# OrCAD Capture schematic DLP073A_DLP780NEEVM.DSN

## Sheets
1 PG05 INPUT FMC CONNECTOR: size D
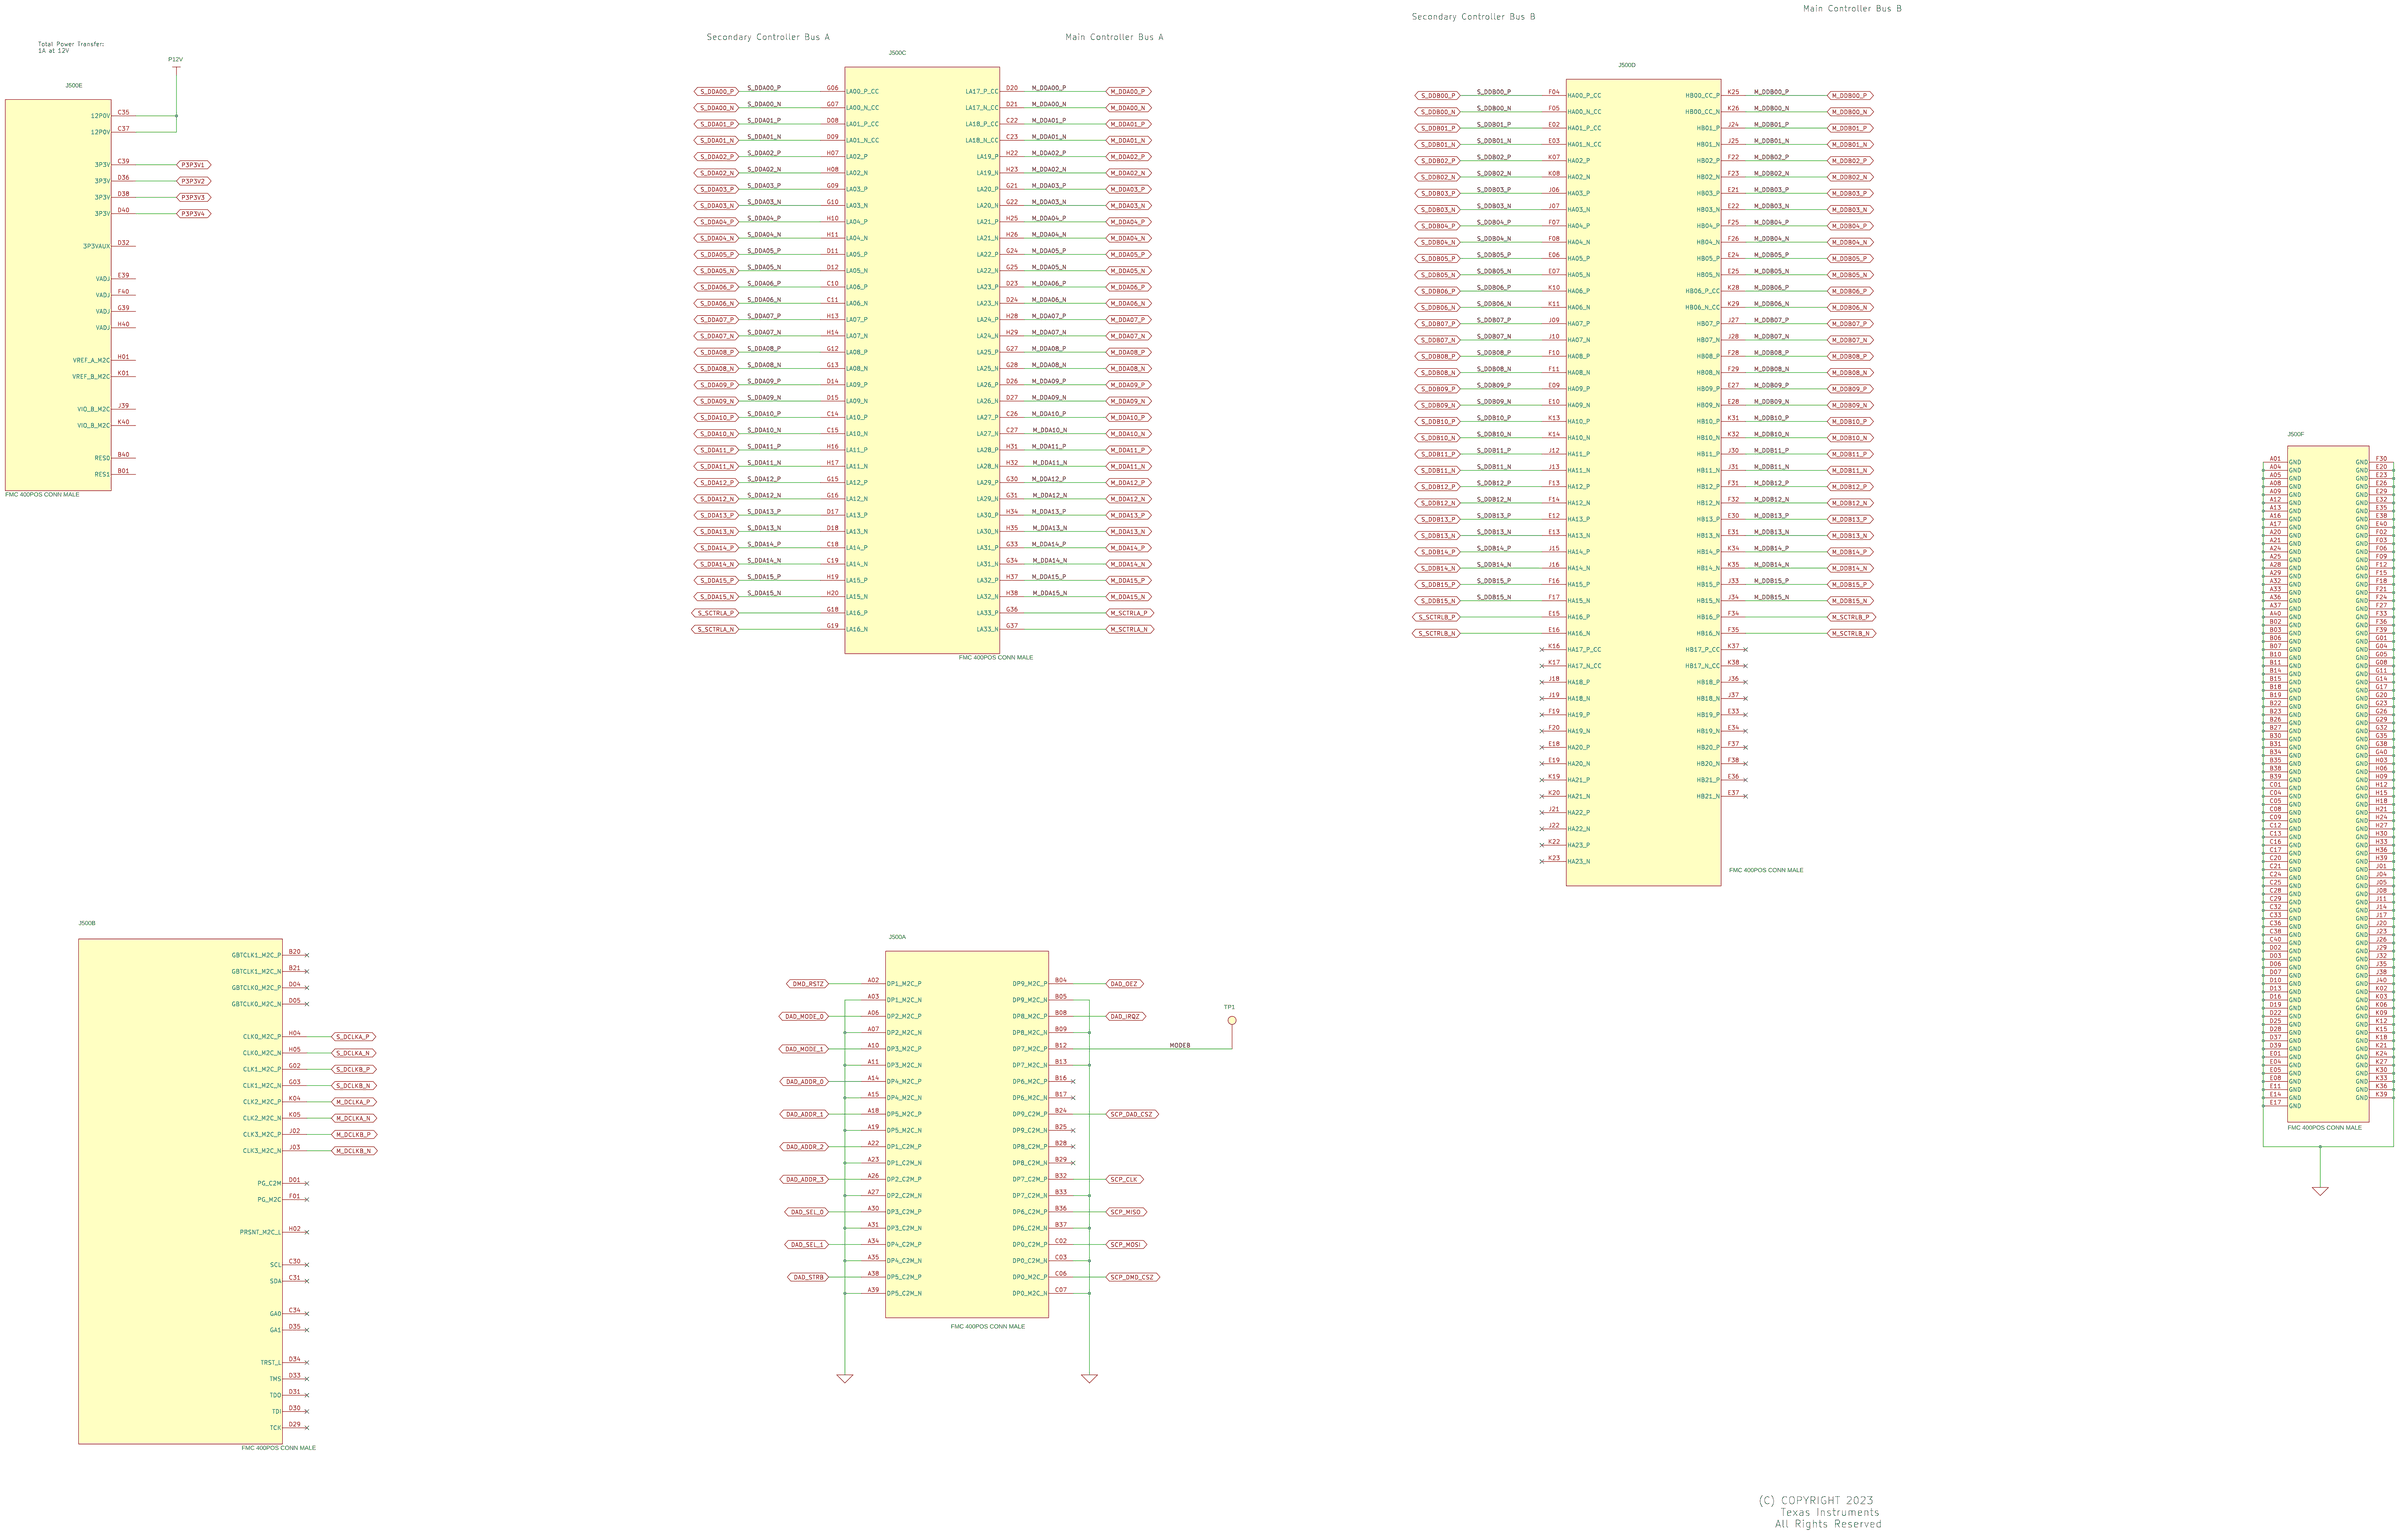
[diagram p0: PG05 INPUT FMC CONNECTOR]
2 PG01 TITLE: rev: D
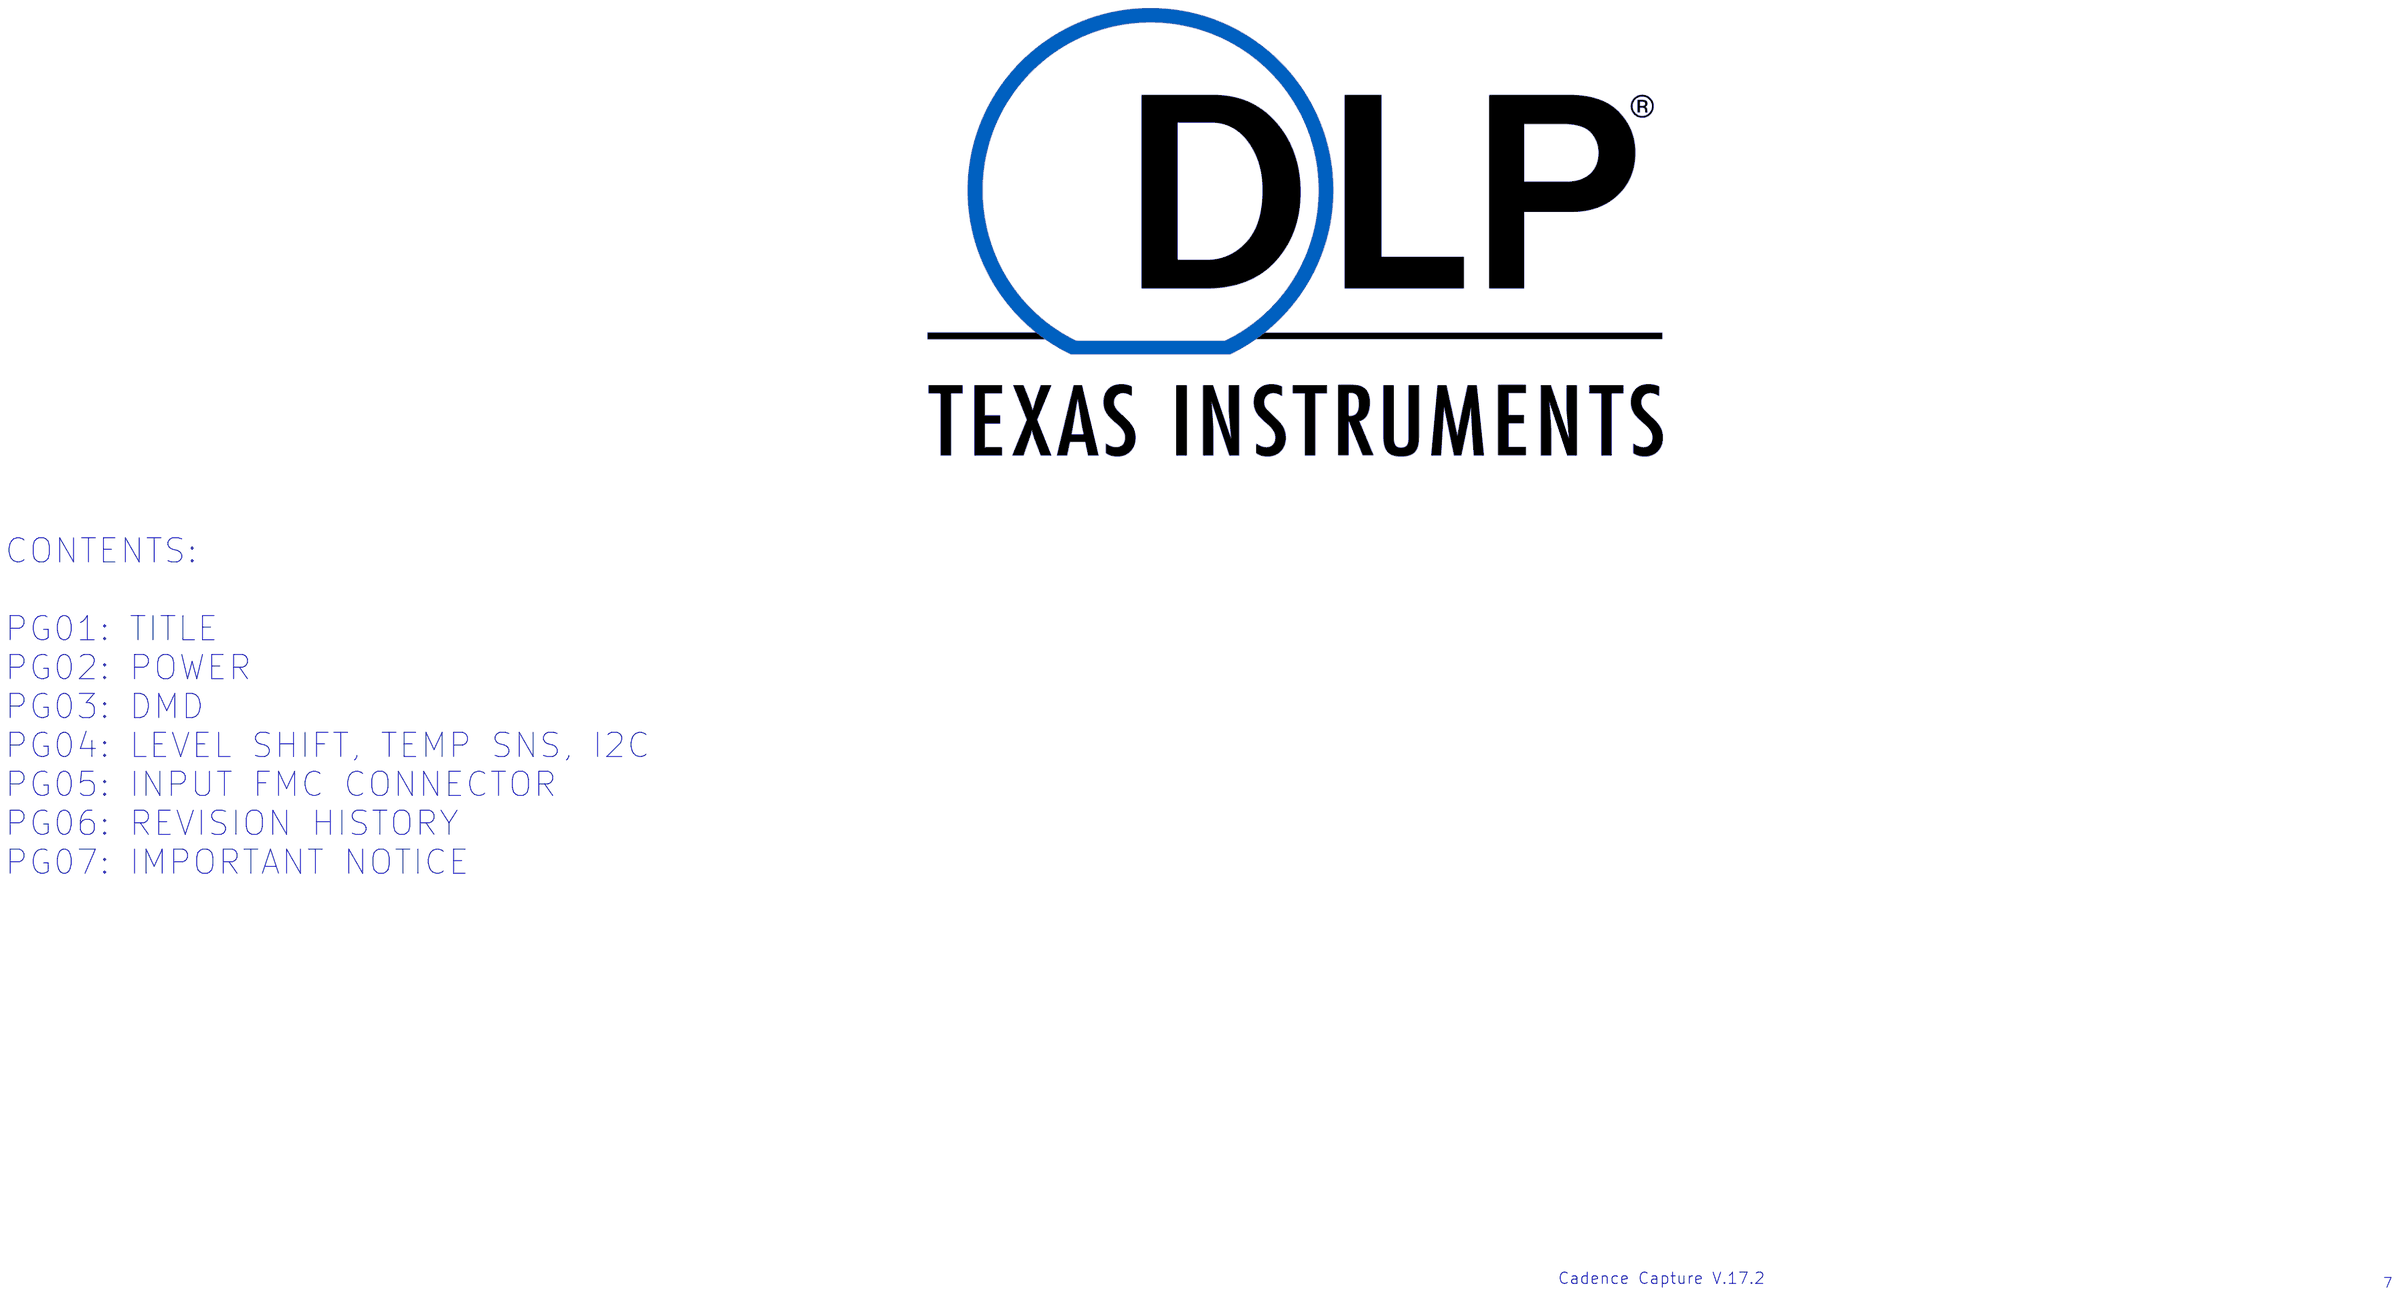
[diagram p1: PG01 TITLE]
3 PG06 REVISION HISTORY: rev: E.2
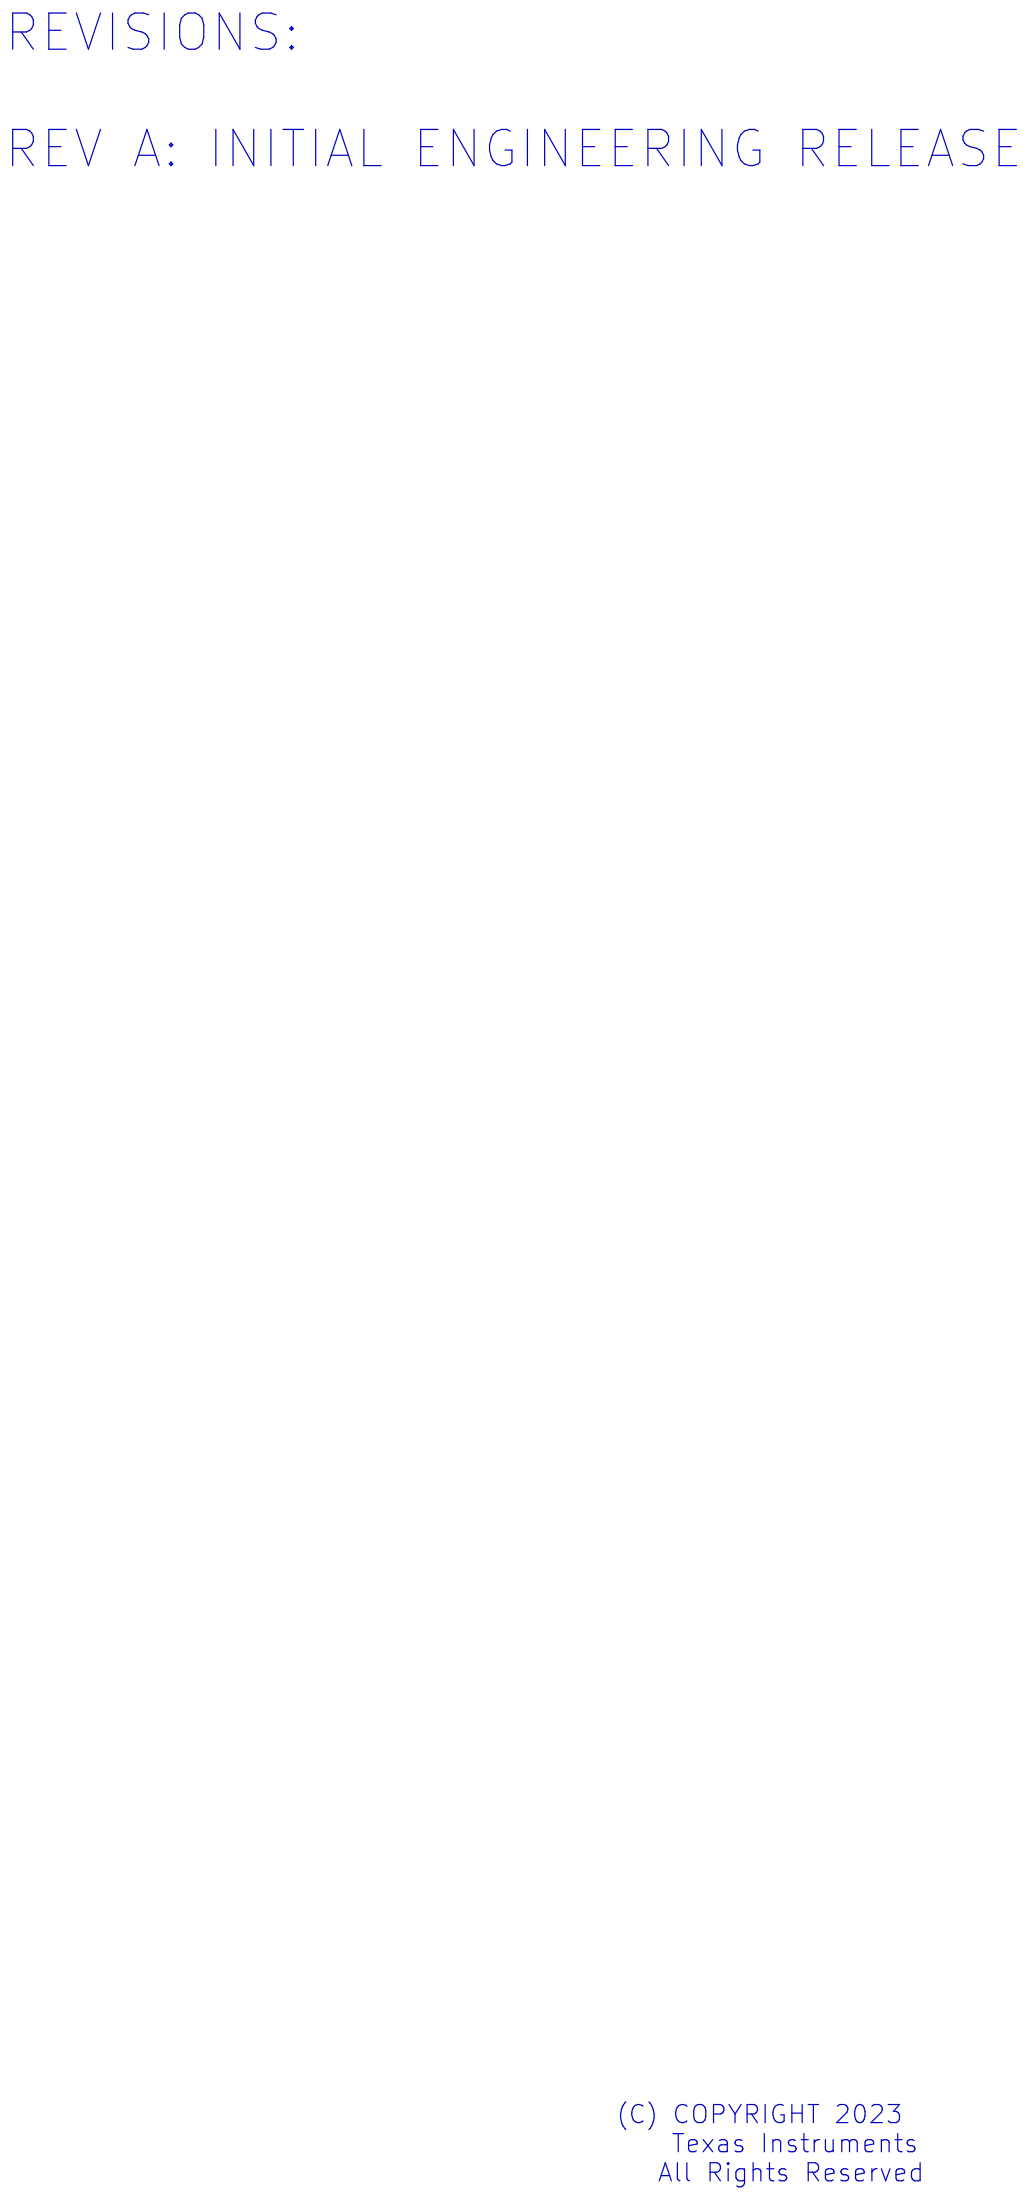
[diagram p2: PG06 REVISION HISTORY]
4 PG02 POWER: size C; rev: E.2
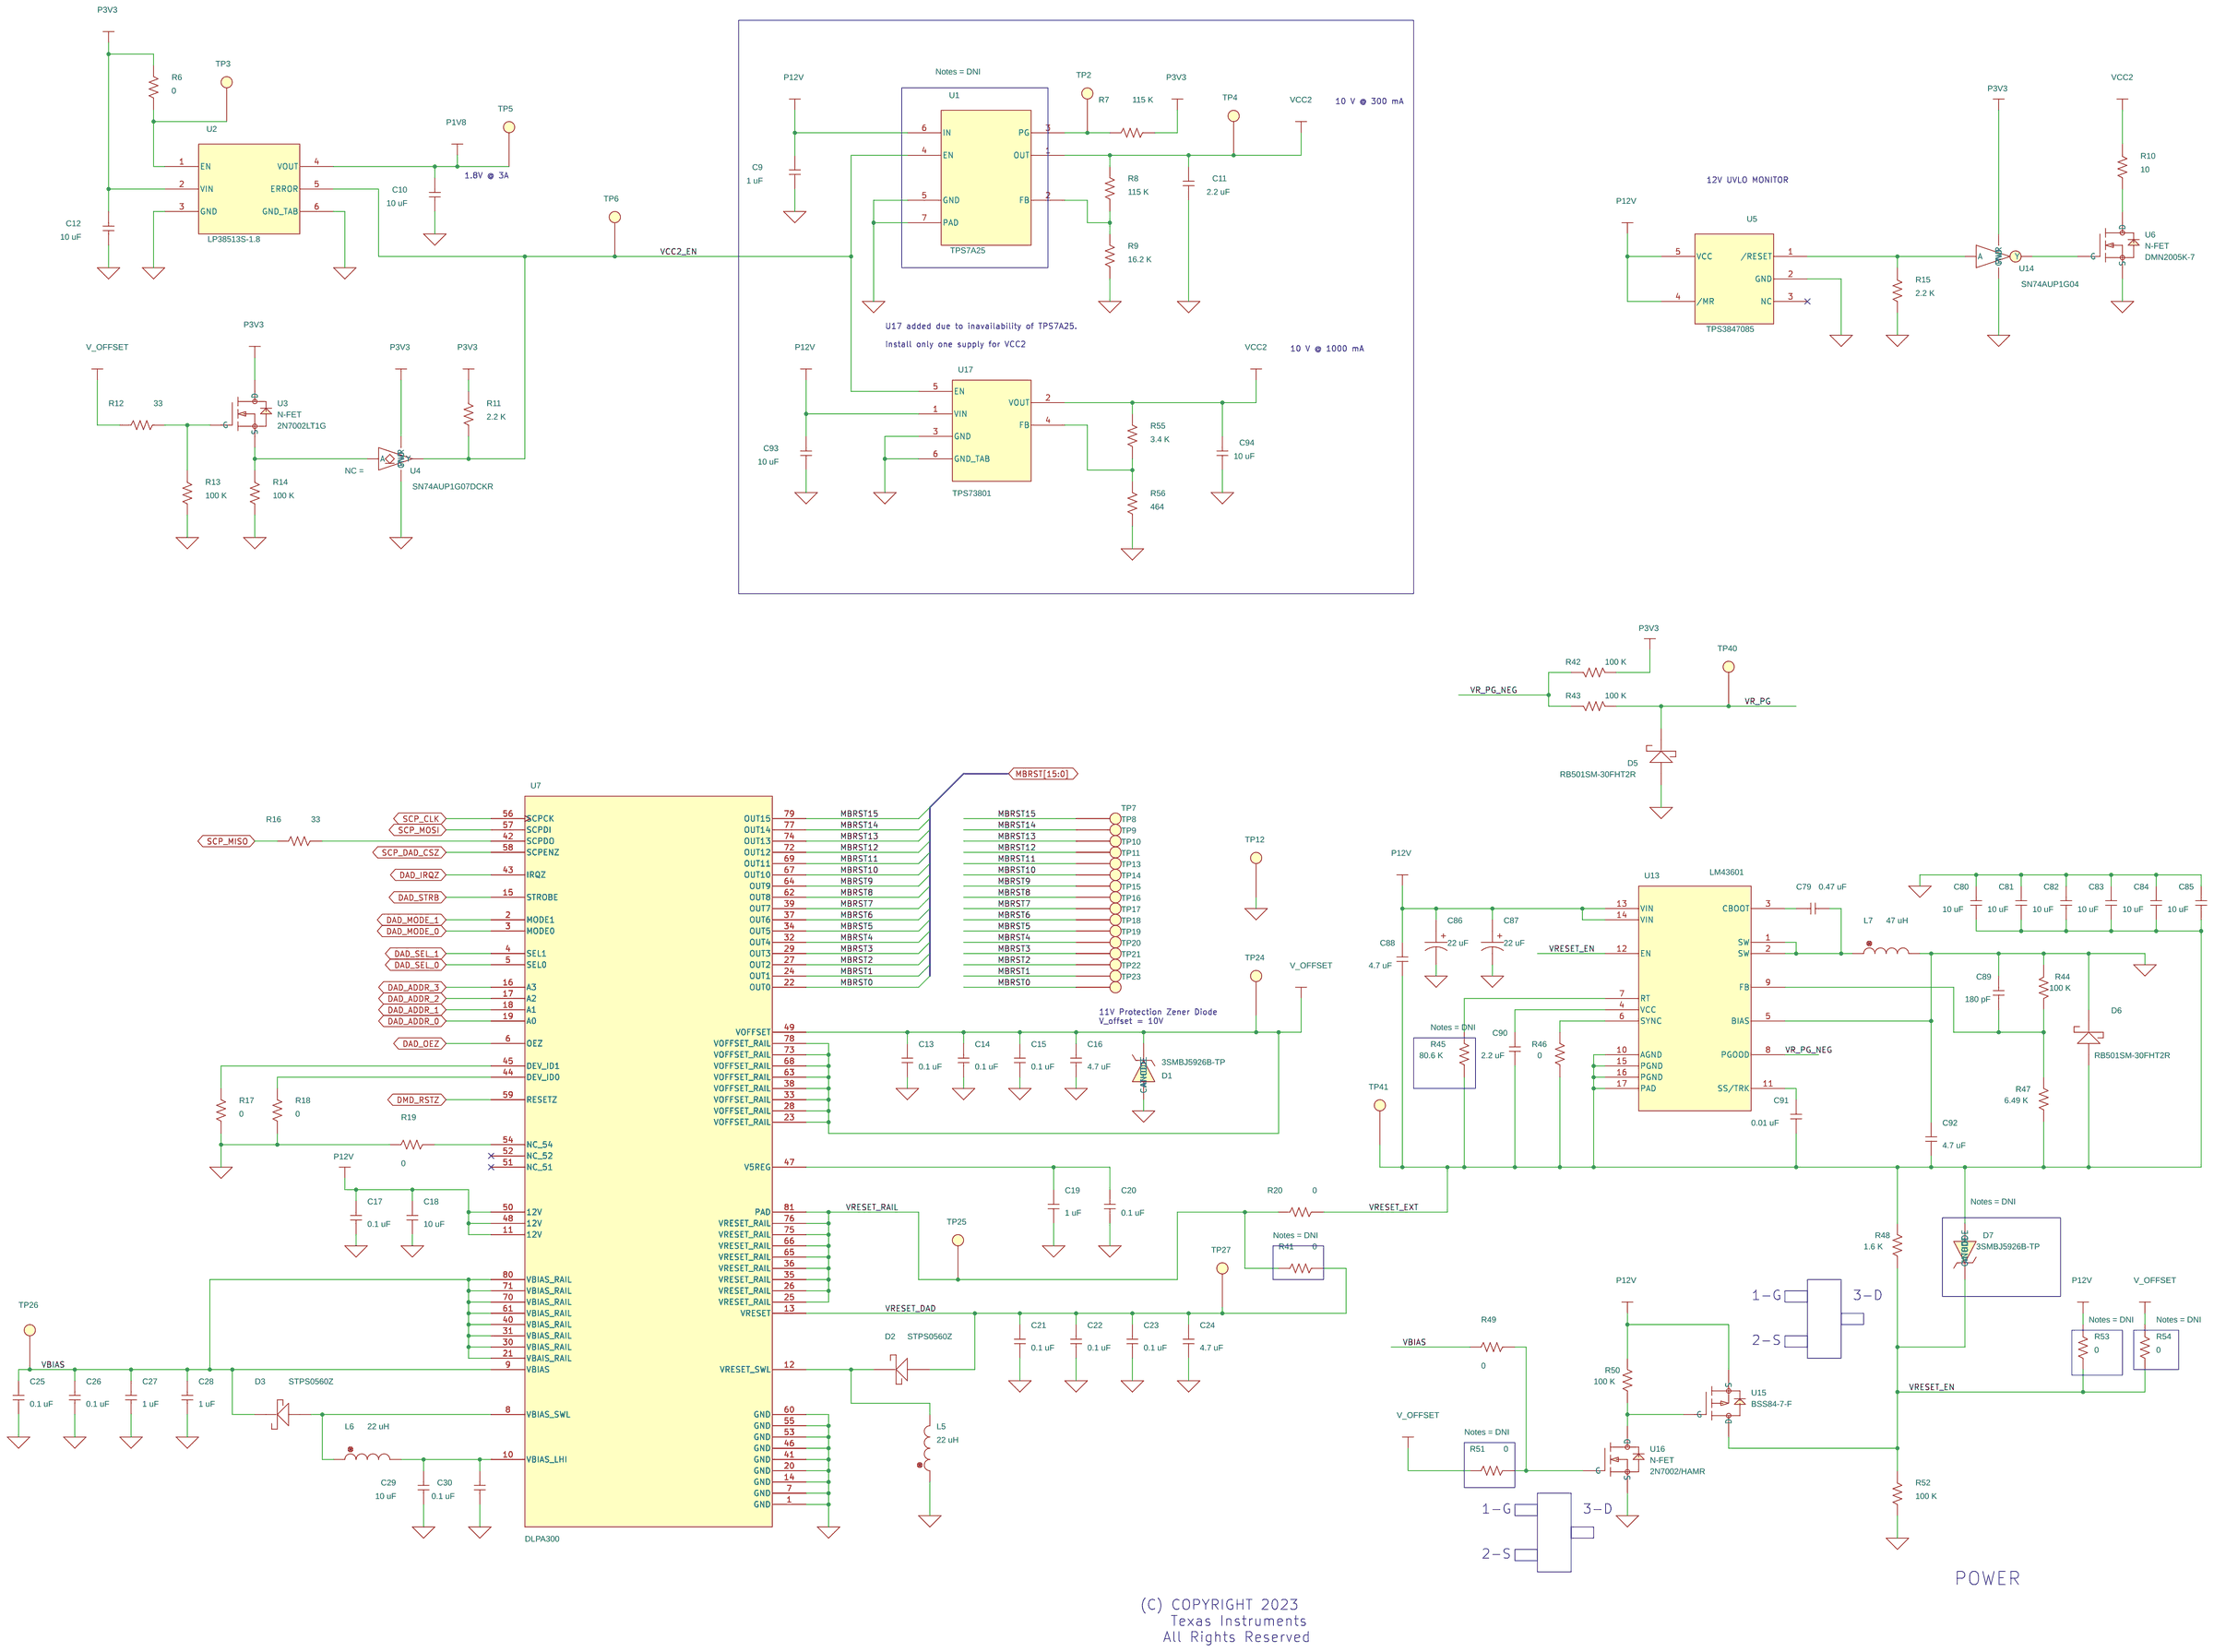
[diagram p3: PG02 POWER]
5 PG03 DMD: size C; rev: E.2
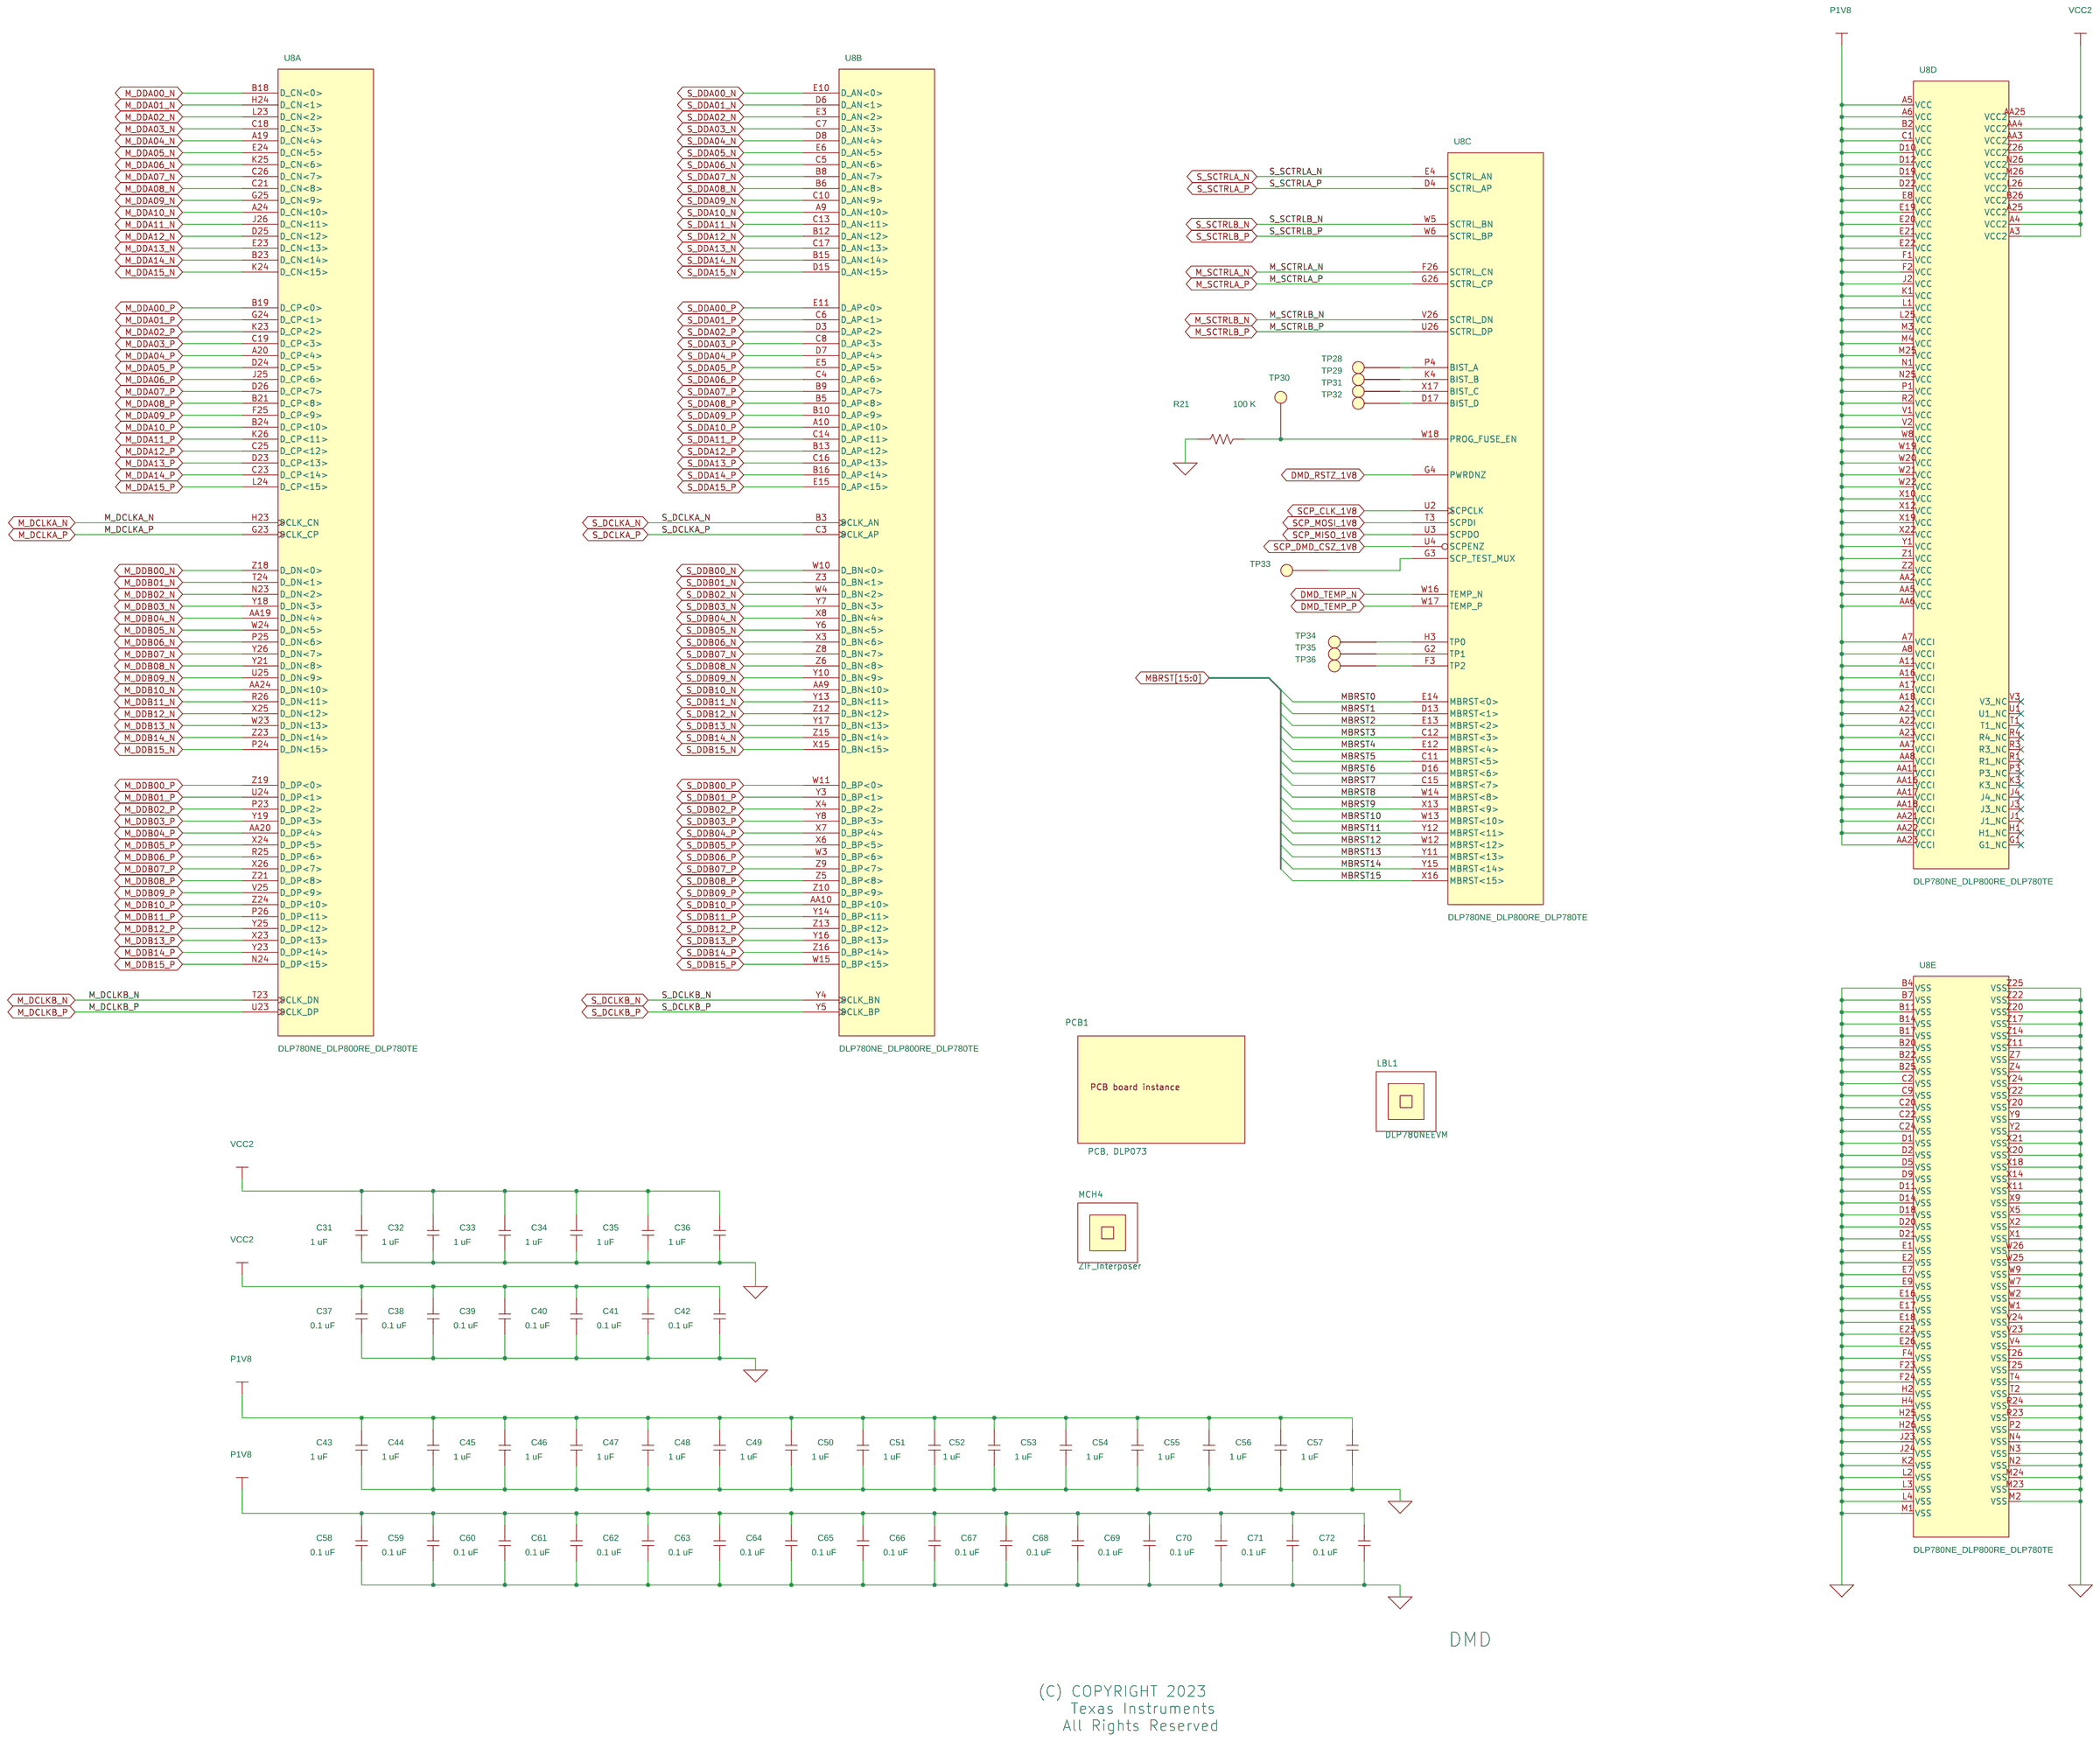
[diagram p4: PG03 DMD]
6 PG04 LEVEL SHIFT, TEMP SNS: size C; rev: E.2
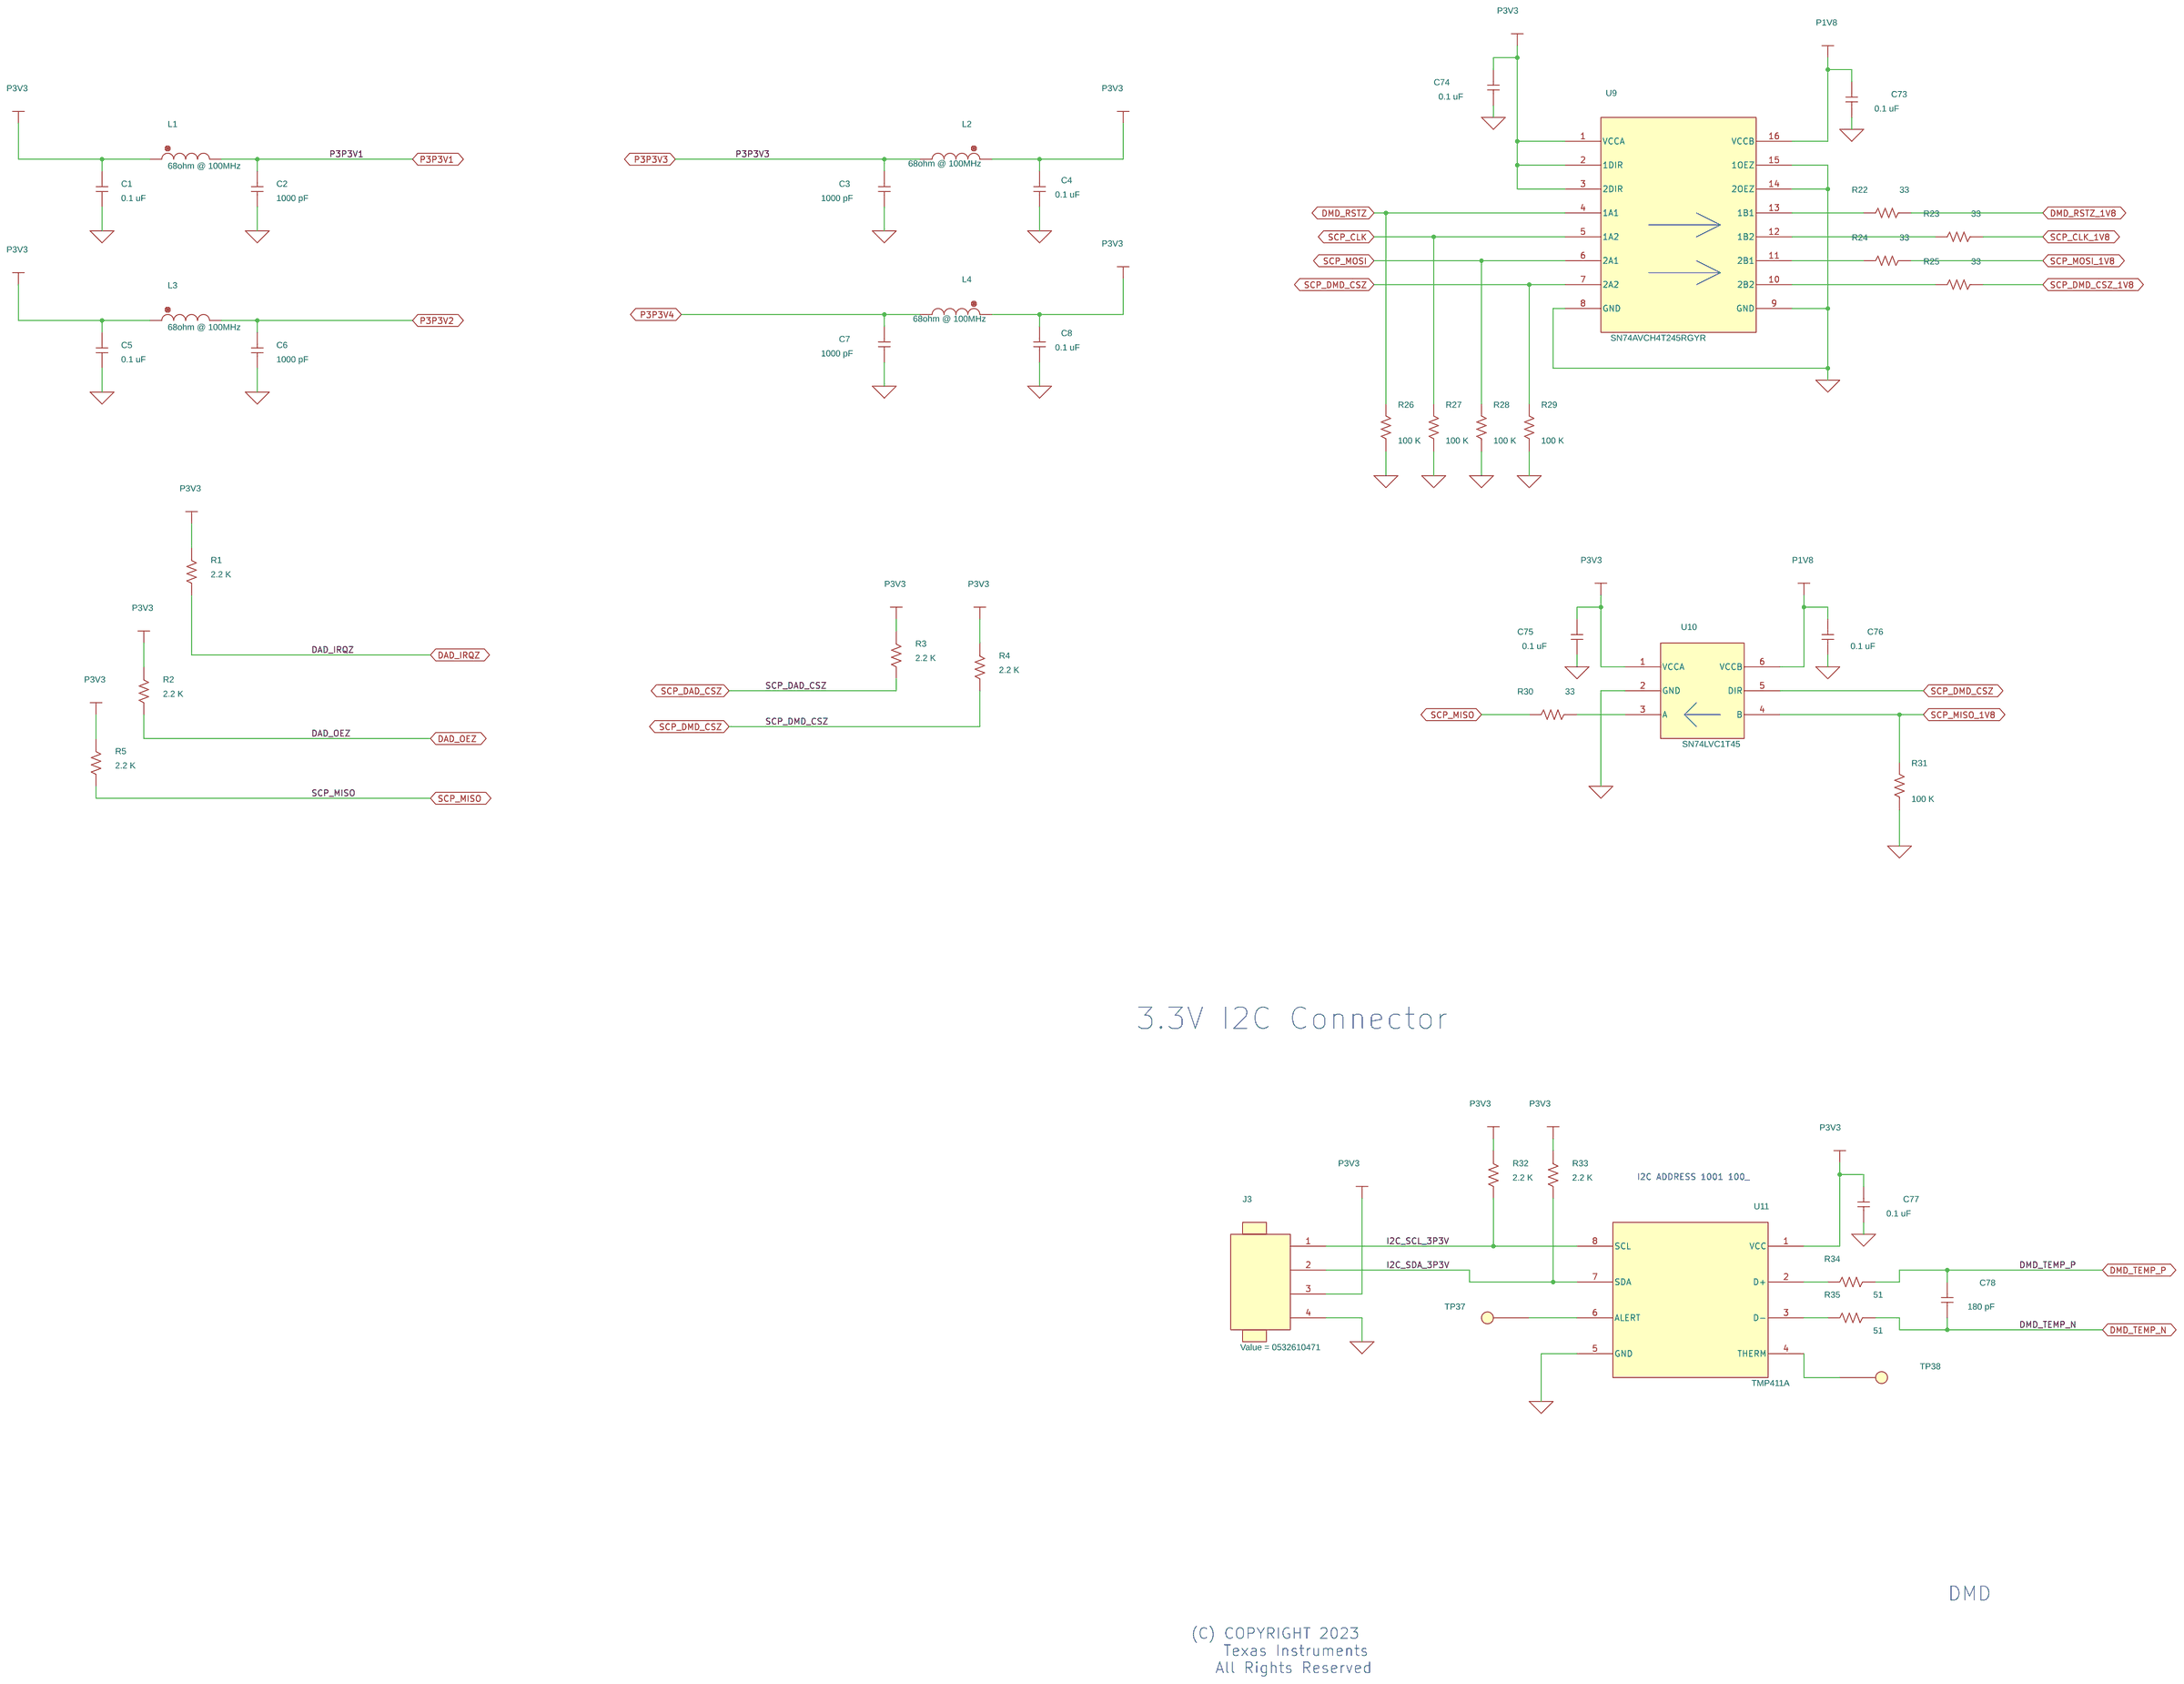
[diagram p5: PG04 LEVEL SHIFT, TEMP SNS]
7 PG07 IMPORTANT NOTICE: rev: E.2
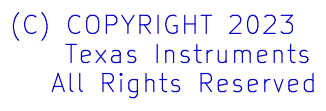
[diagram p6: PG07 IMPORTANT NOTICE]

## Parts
sheet PG02 POWER
C9  1 uF  [0603]
C10  10 uF  [1210]
C11  2.2 uF  [0603]
C12  10 uF  [1210]
C13  0.1 uF  [0603]
C14  0.1 uF  [0603]
C15  0.1 uF  [0603]
C16  4.7 uF  [0805]
C17  0.1 uF  [0603]
C18  10 uF  [1210]
C19  1 uF  [0603]
C20  0.1 uF  [0603]
C21  0.1 uF  [0603]
C22  0.1 uF  [0603]
C23  0.1 uF  [0603]
C24  4.7 uF  [0805]
C25  0.1 uF  [0603]
C26  0.1 uF  [0603]
C27  1 uF  [0603]
C28  1 uF  [0603]
C29  10 uF  [1210]
C30  0.1 uF  [0603]
C79  0.47 uF  [0805]
C80  10 uF  [1210]
C81  10 uF  [1210]
C82  10 uF  [1210]
C83  10 uF  [1210]
C84  10 uF  [1210]
C85  10 uF  [1210]
C86  22 uF  [1411]
C87  22 uF  [1411]
C88  4.7 uF  [0805]
C89  180 pF  [0603]
C90  2.2 uF  [0603]
C91  0.01 uF  [0603]
C92  4.7 uF  [0805]
C93  10 uF  [1210]
C94  10 uF  [1210]
D1  3SMBJ5926B-TP  [DO-214AA]
D2  STPS0560Z  [SOD-123]
D3  STPS0560Z  [SOD-123]
D5  RB501SM-30FHT2R  [SC-79]
D6  RB501SM-30FHT2R  [SC-79]
D7  3SMBJ5926B-TP  [DO-214AA]
L5  22 uH  [Bourns_ww_22uh]
L6  22 uH  [Bourns_ww_22uh]
L7  47 uH  [Bourns_ww_47uh]
R6  0  [0603]
R7  115 K  [0603]
R8  115 K  [0603]
R9  16.2 K  [0603]
R10  10  [0603]
R11  2.2 K  [0603]
R12  33  [0603]
R13  100 K  [0603]
R14  100 K  [0603]
R15  2.2 K  [0603]
R16  33  [0603]
R17  0  [0603]
R18  0  [0603]
R19  0  [0603]
R20  0  [0603]
R41  0  [0603]
R42  100 K  [0603]
R43  100 K  [0603]
R44  100 K  [0603]
R45  80.6 K  [0603]
R46  0  [0603]
R47  6.49 K  [0603]
R48  1.6 K  [0603]
R49  0  [0603]
R50  100 K  [0603]
R51  0  [0603]
R52  100 K  [0603]
R53  0  [0603]
R54  0  [0603]
R55  3.4 K  [0603]
R56  464  [0603]
TP2  Testpoint_via  [TP-48RD28]
TP3  Testpoint_via  [TP-48RD28]
TP4  Testpoint_via  [TP-48RD28]
TP5  Testpoint_via  [TP-48RD28]
TP6  Testpoint_via  [TP-48RD28]
TP7  Testpoint_via  [TP-48RD28]
TP8  Testpoint_via  [TP-48RD28]
TP9  Testpoint_via  [TP-48RD28]
TP10  Testpoint_via  [TP-48RD28]
TP11  Testpoint_via  [TP-48RD28]
TP12  GND Testpoint  [TP-5006-GND_KEY]
TP13  Testpoint_via  [TP-48RD28]
TP14  Testpoint_via  [TP-48RD28]
TP15  Testpoint_via  [TP-48RD28]
TP16  Testpoint_via  [TP-48RD28]
TP17  Testpoint_via  [TP-48RD28]
TP18  Testpoint_via  [TP-48RD28]
TP19  Testpoint_via  [TP-48RD28]
TP20  Testpoint_via  [TP-48RD28]
TP21  Testpoint_via  [TP-48RD28]
TP22  Testpoint_via  [TP-48RD28]
TP23  Testpoint_via  [TP-48RD28]
TP24  Testpoint_via  [TP-48RD28]
TP25  Testpoint_via  [TP-48RD28]
TP26  Testpoint_via  [TP-48RD28]
TP27  Testpoint_via  [TP-48RD28]
TP40  Testpoint_via  [TP-48RD28]
TP41  Testpoint_via  [TP-48RD28]
U1  TPS7A25  [6-WSON]
U2  LP38513S-1.8  [TO-263-6]
U3  N-FET  [SOT-23-3]
U4  SN74AUP1G07DCK  [5-TSSOP]
U5  TPS3847085  [SOT-23-5]
U6  N-FET  [SOT-23-3]
U7  DLPA300  [eTQFP80]
U13  LM43601  [16HTSSOP]
U14  SN74LVC1G04  [U_5_DCK]
U15  BSS84-7-F  [TO-236-3]
U16  N-FET  [SOT-23-3]
U17  TPS73801  [SOT-223-6]
sheet PG03 DMD
C31  1 uF  [0603]
C32  1 uF  [0603]
C33  1 uF  [0603]
C34  1 uF  [0603]
C35  1 uF  [0603]
C36  1 uF  [0603]
C37  0.1 uF  [0603]
C38  0.1 uF  [0603]
C39  0.1 uF  [0603]
C40  0.1 uF  [0603]
C41  0.1 uF  [0603]
C42  0.1 uF  [0603]
C43  1 uF  [0603]
C44  1 uF  [0603]
C45  1 uF  [0603]
C46  1 uF  [0603]
C47  1 uF  [0603]
C48  1 uF  [0603]
C49  1 uF  [0603]
C50  1 uF  [0603]
C51  1 uF  [0603]
C52  1 uF  [0603]
C53  1 uF  [0603]
C54  1 uF  [0603]
C55  1 uF  [0603]
C56  1 uF  [0603]
C57  1 uF  [0603]
C58  0.1 uF  [0603]
C59  0.1 uF  [0603]
C60  0.1 uF  [0603]
C61  0.1 uF  [0603]
C62  0.1 uF  [0603]
C63  0.1 uF  [0603]
C64  0.1 uF  [0603]
C65  0.1 uF  [0603]
C66  0.1 uF  [0603]
C67  0.1 uF  [0603]
C68  0.1 uF  [0603]
C69  0.1 uF  [0603]
C70  0.1 uF  [0603]
C71  0.1 uF  [0603]
C72  0.1 uF  [0603]
LBL1  DLP780NEEVM  [Not-a-part]
MCH4  ZIF_Interposer  [S600]
PCB1  PCB, DLP073  [Not-a-part]
R21  100 K  [0603]
TP28  Testpoint_via  [TP-48RD28]
TP29  Testpoint_via  [TP-48RD28]
TP30  Testpoint_via  [TP-48RD28]
TP31  Testpoint_via  [TP-48RD28]
TP32  Testpoint_via  [TP-48RD28]
TP33  Testpoint_via  [TP-48RD28]
TP34  Testpoint_via  [TP-48RD28]
TP35  Testpoint_via  [TP-48RD28]
TP36  Testpoint_via  [TP-48RD28]
U8  DLP780NE_DLP800RE_DLP780TE  [S600]  (sections A,B,C,D,E)
sheet PG04 LEVEL SHIFT, TEMP SNS
C1  0.1 uF  [0603]
C2  1000 pF  [0402]
C3  1000 pF  [0402]
C4  0.1 uF  [0603]
C5  0.1 uF  [0603]
C6  1000 pF  [0402]
C7  1000 pF  [0402]
C8  0.1 uF  [0603]
C73  0.1 uF  [0603]
C74  0.1 uF  [0603]
C75  0.1 uF  [0603]
C76  0.1 uF  [0603]
C77  0.1 uF  [0603]
C78  180 pF  [0402]
J3  0532610471  [CONN4-53261-A_MOLEX]
L1  68ohm @ 100MHz  [0603]
L2  68ohm @ 100MHz  [0603]
L3  68ohm @ 100MHz  [0603]
L4  68ohm @ 100MHz  [0603]
R1  2.2 K  [0603]
R2  2.2 K  [0603]
R3  2.2 K  [0603]
R4  2.2 K  [0603]
R5  2.2 K  [0603]
R22  33  [0603]
R23  33  [0603]
R24  33  [0603]
R25  33  [0603]
R26  100 K  [0603]
R27  100 K  [0603]
R28  100 K  [0603]
R29  100 K  [0603]
R30  33  [0603]
R31  100 K  [0603]
R32  2.2 K  [0603]
R33  2.2 K  [0603]
R34  51  [0603]
R35  51  [0603]
TP37  Testpoint_via  [TP-48RD28]
TP38  Testpoint_via  [TP-48RD28]
U9  SN74AVCH4T245RGYR  [VQFN]
U10  SN74LVC1T45  [6-TSSOP]
U11  TMP411A  [SOIC8-DGK_TI]
sheet PG05 INPUT FMC CONNECTOR
J500  FMC 400POS CONN MALE  [CONN400-SEAM-40-A-A_SAM-ALPHA]  (sections A,B,C,D,E,F)
TP1  Testpoint_via  [TP-48RD28]

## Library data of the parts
C9 C19 C27 C28 C31-C36 C43-C57 = C: DIELECTRIC: X5R; MFG: Samsung; PART NUMBER: CL10A105KB8NNNC; Rating: 50 V; TOLERANCE: 10%
C10 C12 C18 C29 C93 C94 = C: DIELECTRIC: X7S; MFG: Murata; PART NUMBER: GCM32EC71H106KA03L; Rating: 50 V; TOLERANCE: 10%
C11 C90 = C: MFG: Murata; PART NUMBER: GRM188R61H225KE11D; Rating: 50 V; TOLERANCE: 10%
C1 C4 C5 C8 C13-C15 C17 C20-C23 C25 C26 C30 C37-C42 C58-C72 = C: DIELECTRIC: X7R; MFG: KEMET; PART NUMBER: C0603C104M5RACTU; Rating: 50 V; TOLERANCE: 20%
C16 C24 = C: DIELECTRIC: X5R; MFG: Murata; PART NUMBER: GRM21BR61H475KE51L; Rating: 50 V; TOLERANCE: 10%
C79 = C: MFG: Samsung; PART NUMBER: CL21B474KBFNFNE; Rating: 50 V; TOLERANCE: 10%
C80-C85 = C: MFG: Murata; PART NUMBER: GCM32EC71H106KA03L; Rating: 50 V; TOLERANCE: 10%
C86 C87 = CAPACITOR_POL_0: DigiKey Part Number: PCE5115CT-ND; MFG: Panasonic; PART NUMBER: 20TQC22MYFB; Rating: 20 V; TOLERANCE: 20%; VOLTAGE: 16V
C88 C92 = C: MFG: Murata; PART NUMBER: GRM21BR61H475KE51L; Rating: 50 V; TOLERANCE: 10%
C89 = C: MFG: AVX; PART NUMBER: 06035A181JAT2A; Rating: 50 V; TOLERANCE: 5%
C91 = C: MFG: Samsung; PART NUMBER: CL10B103KB8NNNC; Rating: 50 V; TOLERANCE: 10%
D1 = DIODE_SCHOTTKY_dsize_0: Diode Schottky; DigiKey Part Number: CUS10S30H3FCT-ND; Mfg: Micro Commercial; Rating: 11 V
D2 D3 = SCHOTTKY_DIODE: MFG: STMicroelectronics; POWER: 500 mA
D5 D6 = SCHOTTKY_DIODE: MFG: Rohm; Rating: 30 V 100 mA
D7 = DIODE_SCHOTTKY_dsize_0: Diode Schottky; DigiKey Part Number: CUS10S30H3FCT-ND; Mfg: Micro Commercial; Notes: DNI; Rating: 11 V
L5 L6 = L: MFG: Bourns; PART NUMBER: SRU5018-220Y; Rating: 680 mA; TOLERANCE: 30%
L7 = L: MFG: Bourns; PART NUMBER: SRN8040-470M; Rating: 1.4 A
R6 R17-R20 R46 R49 = R: DigiKey Part Number: P12JCT-ND; MFG: Panasonic; PART NUMBER: ERJ-3GEY0R00V; Rating: 0.1 W
R7 R8 = R: DigiKey Part Number: P12JCT-ND; MFG: Panasonic; PART NUMBER: ERJ-3EKF1153V; Rating: 0.1 W; TOLERANCE: 1%
R9 = R: DigiKey Part Number: P12JCT-ND; MFG: Yageo; PART NUMBER: RC0603FR-0716K2L; Rating: 0.1 W; TOLERANCE: 1%
R10 = R: DigiKey Part Number: P12JCT-ND; MFG: Yageo; PART NUMBER: RC0603FR-0710RL; Rating: 0.1 W; TOLERANCE: 5%
R1-R5 R11 R15 R32 R33 = R: DigiKey Part Number: P12JCT-ND; MFG: Panasonic; PART NUMBER: ERJ-3GEYJ222V; Rating: 0.1 W; TOLERANCE: 5%
R12 R16 R22-R25 R30 = R: DigiKey Part Number: P12JCT-ND; MFG: Yageo; PART NUMBER: RC0603JR-0733RL; Rating: 0.1 W; TOLERANCE: 5%
R13 R14 R21 R26-R29 R31 R42-R44 R50 R52 = R: DigiKey Part Number: P12JCT-ND; MFG: Panasonic; PART NUMBER: ERJ-3GEYJ104V; Rating: 0.1 W; TOLERANCE: 5%
R41 R51 R53 R54 = R: DigiKey Part Number: P12JCT-ND; MFG: Panasonic; Notes: DNI; PART NUMBER: ERJ-3GEY0R00V; Rating: 0.1 W
R45 = R: DigiKey Part Number: P12JCT-ND; MFG: Panasonic; Notes: DNI; PART NUMBER: ERJ-3EKF8062V; Rating: 0.1 W; TOLERANCE: 1%
R47 = R: DigiKey Part Number: P12JCT-ND; MFG: Panasonic; PART NUMBER: ERA-3AEB6491V; Rating: 0.1 W; TOLERANCE: 0.1%
R48 = R: DigiKey Part Number: P12JCT-ND; MFG: Panasonic; PART NUMBER: ERJ-3GEYJ162V; Rating: 0.1 W; TOLERANCE: 5%
R55 = R: DigiKey Part Number: P12JCT-ND; MFG: Panasonic; PART NUMBER: ERJ-3EKF3401V; Rating: 0.1 W; TOLERANCE: 1%
R56 = R: DigiKey Part Number: P12JCT-ND; MFG: Panasonic; PART NUMBER: ERJ-3EKF4640V; Rating: 0.1 W; TOLERANCE: 1%
TP1-TP11 TP13-TP38 TP40 TP41 = Testpoint: MFG: Not-a-part; Notes: 28mil_via; PART NUMBER: Not-a-part
TP12 = Testpoint: DigiKey Part Number: 36-5006-ND; MFG: Keystone; PART NUMBER: 5006
U1 = TPS7A25: MFG: Texas Instruments; Notes: DNI; PART NUMBER: TPS7A2501DRVT
U2 = LP38513S-1.8: MFG: Texas Instruments; PART NUMBER: LP38513S-1.8/NOPB
U3 = N-FET_0: MOSFET, N-Channel; DigiKey Part Number: DMN67D8L-7DICT-ND; MFG: On Semiconductor; Part Number: 2N7002LT1G; RATING: 225 mW
U4 = TMP_083607: DigiKey: 296-18256-1-ND; Family: logic; Index PN: 1027; Lead Style: SMT; MFG: Texas Instruments; P/D_NUM: SN74AUP1G07DCKR; Part Number: SN74AUP1G07DCKR; Part Specific: IC BUFF/DVR LOW PWR N-INV SC705  open drain; Type: buffer
U5 = TPS3847085: MFG: Texas Instruments; PART NUMBER: TPS3847085DBVR
U6 = N-FET_0: MOSFET, N-Channel; DigiKey Part Number: DMN67D8L-7DICT-ND; MFG: Diodes Inc; Part Number: DMN2005K-7; RATING: 350 mW
U7 = DLPA300_0: MFG: Texas Instruments
U13 = LM43601: MFG: Texas Instruments; PART NUMBER: LM43601PWPR
U14 = SN74LVC1G04_0: MFG: Texas Instruments; P/D_NUM: SN74AUP1G04; PART NUMBER: SN74AUP1G04DCKT
U15 = P-FET_0: MFG: Diodes Inc; Rating: 130 mA
U16 = N-FET_0: MOSFET, N-Channel; DigiKey Part Number: DMN67D8L-7DICT-ND; MFG: Nexperia; Part Number: 2N7002/HAMR; RATING: 300 mA
U17 = TPS73801_0: MFG: Texas Instruments; PART NUMBER: TPS73801DCQR; Rating: 1 A
LBL1 = PCB_2: Thermal Transfer Printable Labels, 0.65"W x 0.20"H - 10,000 per roll; Assembly Notes: Label Final Assy "DLPLCR90EVM"; MFG: Brady; Manuf: Brady; Notes: DNI; Part Number: THT-14-423-10
MCH4 = PCB_2: Interposer, DMD, S600; Assembly Notes: Solder during assembly; Manuf: Foxconn Interconnect Technology; Mfg: Foxconn Interconnect Technology; Part Number: PZ35021-2641-01H
PCB1 = DLP028_0: Board Instance; MFG: Any; Notes: DNI; Part Number: DLP062
U8 = DLP80RE_DLP78NE: MFG: Texas Instruments
C2 C3 C6 C7 = C: DIELECTRIC: X7R; MFG: Yageo; PART NUMBER: CC0402KRX7R9BB102; Rating: 50 V; TOLERANCE: 10%
C73-C77 = C: DIELECTRIC: X7R; DigiKey Part Number: 445-6899-1-ND; MFG: KEMET; PART NUMBER: C0603C104M5RACTU; Rating: 50 V; TOLERANCE: 20%; VOLTAGE: 50 V
C78 = C: DIELECTRIC: X7R; DigiKey Part Number: 445-1250-1-ND; MFG: Samsung; PART NUMBER: CL05B181KB5NNNC; Rating: 50 V; TOLERANCE: 10%; VOLTAGE: 50V
J3 = Conn_4: Connector, 4 Pin; DigiKey Part Number: WM7622CT-ND; MFG: Molex; Part Number: 053261-0471
L1-L4 = L: MFG: Laird; PART NUMBER: MI0603J680R-10; Rating: 1 A
R34 R35 = R: DigiKey Part Number: P51.0HCT-ND; MFG: Panasonic; PART NUMBER: ERJ-3EKF51R0V; Rating: 0.1 W; TOLERANCE: 1%
U9 = SN74AVCH4T245RGYR: IC, Level Translator; MFG: Texas Instruments
U10 = SN74LVC1T45: MFG: Texas Instruments; PART NUMBER: SN74LVC1T45DCKT
U11 = TMP411: DigiKey Part Number: 296-36780-1-ND; MFG: Texas Instruments; PART NUMBER: TMP411AQDGKRQ1
J500 = FMC_400POS_CONNECTOR: MFG: Samtec; PART NUMBER: SEAM-40-11.0-S-10-2-A-K-TR

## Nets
GND: C1.1 C2.1 C3.1 C4.1 C5.1 C6.1 C7.1 C8.1 C9.1 C10.1 C11.1 C12.1 C13.1 C14.1 C15.1 C16.1 C17.1 C18.1 C19.1 C20.1 C21.1 C22.1 C23.1 C24.1 C25.1 C26.1 C27.1 C28.1 C29.1 C30.1 C31.1 C32.1 C33.1 C34.1 C35.1 C36.1 C37.1 C38.1 C39.1 C40.1 C41.1 C42.1 C43.1 C44.1 C45.1 C46.1 C47.1 C48.1 C49.1 C50.1 C51.1 C52.1 C53.1 C54.1 C55.1 C56.1 C57.1 C58.1 C59.1 C60.1 C61.1 C62.1 C63.1 C64.1 C65.1 C66.1 C67.1 C68.1 C69.1 C70.1 C71.1 C72.1 C73.1 C74.1 C75.1 C76.1 C77.1 C80.2 C81.2 C82.2 C83.2 C84.2 C85.2 C86.2 C87.2 C89.2 C92.2 C93.1 C94.1 D1.1(ANODE) D5.A D6.C J3.4 J500.A01(GND) J500.A03(DP1_M2C_N) J500.A04(GND) J500.A05(GND) J500.A07(DP2_M2C_N) J500.A08(GND) J500.A09(GND) J500.A11(DP3_M2C_N) J500.A12(GND) J500.A13(GND) J500.A15(DP4_M2C_N) J500.A16(GND) J500.A17(GND) J500.A19(DP5_M2C_N) J500.A20(GND) J500.A21(GND) J500.A23(DP1_C2M_N) J500.A24(GND) J500.A25(GND) J500.A27(DP2_C2M_N) J500.A28(GND) J500.A29(GND) J500.A31(DP3_C2M_N) J500.A32(GND) J500.A33(GND) J500.A35(DP4_C2M_N) J500.A36(GND) J500.A37(GND) J500.A39(DP5_C2M_N) J500.A40(GND) J500.B02(GND) J500.B03(GND) J500.B05(DP9_M2C_N) J500.B06(GND) J500.B07(GND) J500.B09(DP8_M2C_N) J500.B10(GND) J500.B11(GND) J500.B13(DP7_M2C_N) J500.B14(GND) J500.B15(GND) J500.B18(GND) J500.B19(GND) J500.B22(GND) J500.B23(GND) J500.B26(GND) J500.B27(GND) J500.B30(GND) J500.B31(GND) J500.B33(DP7_C2M_N) J500.B34(GND) J500.B35(GND) J500.B37(DP6_C2M_N) J500.B38(GND) J500.B39(GND) J500.C01(GND) J500.C03(DP0_C2M_N) J500.C04(GND) J500.C05(GND) J500.C07(DP0_M2C_N) J500.C08(GND) J500.C09(GND) J500.C12(GND) J500.C13(GND) J500.C16(GND) J500.C17(GND) J500.C20(GND) J500.C21(GND) J500.C24(GND) J500.C25(GND) J500.C28(GND) J500.C29(GND) J500.C32(GND) J500.C33(GND) J500.C36(GND) J500.C38(GND) J500.C40(GND) J500.D02(GND) J500.D03(GND) J500.D06(GND) J500.D07(GND) J500.D10(GND) J500.D13(GND) J500.D16(GND) J500.D19(GND) J500.D22(GND) J500.D25(GND) J500.D28(GND) J500.D37(GND) J500.D39(GND) J500.E01(GND) J500.E04(GND) J500.E05(GND) J500.E08(GND) J500.E11(GND) J500.E14(GND) J500.E17(GND) J500.E20(GND) J500.E23(GND) J500.E26(GND) J500.E29(GND) J500.E32(GND) J500.E35(GND) J500.E38(GND) J500.E40(GND) J500.F02(GND) J500.F03(GND) J500.F06(GND) J500.F09(GND) J500.F12(GND) J500.F15(GND) J500.F18(GND) J500.F21(GND) J500.F24(GND) J500.F27(GND) J500.F30(GND) J500.F33(GND) J500.F36(GND) J500.F39(GND) J500.G01(GND) J500.G04(GND) J500.G05(GND) J500.G08(GND) J500.G11(GND) J500.G14(GND) J500.G17(GND) J500.G20(GND) J500.G23(GND) J500.G26(GND) J500.G29(GND) J500.G32(GND) J500.G35(GND) J500.G38(GND) J500.G40(GND) J500.H03(GND) J500.H06(GND) J500.H09(GND) J500.H12(GND) J500.H15(GND) J500.H18(GND) J500.H21(GND) J500.H24(GND) J500.H27(GND) J500.H30(GND) J500.H33(GND) J500.H36(GND) J500.H39(GND) J500.J01(GND) J500.J04(GND) J500.J05(GND) J500.J08(GND) J500.J11(GND) J500.J14(GND) J500.J17(GND) J500.J20(GND) J500.J23(GND) J500.J26(GND) J500.J29(GND) J500.J32(GND) J500.J35(GND) J500.J38(GND) J500.J40(GND) J500.K02(GND) J500.K03(GND) J500.K06(GND) J500.K09(GND) J500.K12(GND) J500.K15(GND) J500.K18(GND) J500.K21(GND) J500.K24(GND) J500.K27(GND) J500.K30(GND) J500.K33(GND) J500.K36(GND) J500.K39(GND) L5.1 L7.2 R9.1 R13.2 R14.2 R15.2 R17.1 R18.1 R19.2 R21.1 R26.1 R27.1 R28.1 R29.1 R31.1 R44.1 R52.2 R56.1 TP12.1 U1.5(GND) U1.7(PAD) U2.3(GND) U2.6(GND_TAB) U4.3(GND) U5.2(GND) U6.2(S) U7.1(GND) U7.7(GND) U7.14(GND) U7.20(GND) U7.41(GND) U7.46(GND) U7.53(GND) U7.55(GND) U7.60(GND) U8.B4(VSS) U8.B7(VSS) U8.B11(VSS) U8.B14(VSS) U8.B17(VSS) U8.B20(VSS) U8.B22(VSS) U8.B25(VSS) U8.C2(VSS) U8.C9(VSS) U8.C20(VSS) U8.C22(VSS) U8.C24(VSS) U8.D1(VSS) U8.D2(VSS) U8.D5(VSS) U8.D9(VSS) U8.D11(VSS) U8.D14(VSS) U8.D18(VSS) U8.D20(VSS) U8.D21(VSS) U8.E1(VSS) U8.E2(VSS) U8.E7(VSS) U8.E9(VSS) U8.E16(VSS) U8.E17(VSS) U8.E18(VSS) U8.E25(VSS) U8.E26(VSS) U8.F4(VSS) U8.F23(VSS) U8.F24(VSS) U8.H2(VSS) U8.H4(VSS) U8.H25(VSS) U8.H26(VSS) U8.J23(VSS) U8.J24(VSS) U8.K2(VSS) U8.L2(VSS) U8.L3(VSS) U8.L4(VSS) U8.M1(VSS) U8.M2(VSS) U8.M23(VSS) U8.M24(VSS) U8.N2(VSS) U8.N3(VSS) U8.N4(VSS) U8.P2(VSS) U8.R23(VSS) U8.R24(VSS) U8.T2(VSS) U8.T4(VSS) U8.T25(VSS) U8.T26(VSS) U8.V4(VSS) U8.V23(VSS) U8.V24(VSS) U8.W1(VSS) U8.W2(VSS) U8.W7(VSS) U8.W9(VSS) U8.W25(VSS) U8.W26(VSS) U8.X1(VSS) U8.X2(VSS) U8.X5(VSS) U8.X9(VSS) U8.X11(VSS) U8.X14(VSS) U8.X18(VSS) U8.X20(VSS) U8.X21(VSS) U8.Y2(VSS) U8.Y9(VSS) U8.Y20(VSS) U8.Y22(VSS) U8.Y24(VSS) U8.Z4(VSS) U8.Z7(VSS) U8.Z11(VSS) U8.Z14(VSS) U8.Z17(VSS) U8.Z20(VSS) U8.Z22(VSS) U8.Z25(VSS) U9.8(GND) U9.9(GND) U9.14(2OEZ) U9.15(1OEZ) U10.2(GND) U11.5(GND) U13.5(BIAS) U14.3(GND) U16.2(S) U17.3(GND) U17.6(GND_TAB)
P1V8: C10.2 C43.2 C44.2 C45.2 C46.2 C47.2 C48.2 C49.2 C50.2 C51.2 C52.2 C53.2 C54.2 C55.2 C56.2 C57.2 C58.2 C59.2 C60.2 C61.2 C62.2 C63.2 C64.2 C65.2 C66.2 C67.2 C68.2 C69.2 C70.2 C71.2 C72.2 C73.2 C76.2 TP5.1 U2.4(VOUT) U8.A5(VCC) U8.A6(VCC) U8.A7(VCCI) U8.A8(VCCI) U8.A11(VCCI) U8.A16(VCCI) U8.A17(VCCI) U8.A18(VCCI) U8.A21(VCCI) U8.A22(VCCI) U8.A23(VCCI) U8.AA2(VCC) U8.AA5(VCC) U8.AA6(VCC) U8.AA7(VCCI) U8.AA8(VCCI) U8.AA11(VCCI) U8.AA16(VCCI) U8.AA17(VCCI) U8.AA18(VCCI) U8.AA21(VCCI) U8.AA22(VCCI) U8.AA23(VCCI) U8.B2(VCC) U8.C1(VCC) U8.D10(VCC) U8.D12(VCC) U8.D19(VCC) U8.D22(VCC) U8.E8(VCC) U8.E19(VCC) U8.E20(VCC) U8.E21(VCC) U8.E22(VCC) U8.F1(VCC) U8.F2(VCC) U8.J2(VCC) U8.K1(VCC) U8.L1(VCC) U8.L25(VCC) U8.M3(VCC) U8.M4(VCC) U8.M25(VCC) U8.N1(VCC) U8.N25(VCC) U8.P1(VCC) U8.R2(VCC) U8.V1(VCC) U8.V2(VCC) U8.W8(VCC) U8.W19(VCC) U8.W20(VCC) U8.W21(VCC) U8.W22(VCC) U8.X10(VCC) U8.X12(VCC) U8.X19(VCC) U8.X22(VCC) U8.Y1(VCC) U8.Z1(VCC) U8.Z2(VCC) U9.16(VCCB) U10.6(VCCB)
P3V3: C1.2 C4.2 C5.2 C8.2 C12.2 C74.2 C75.2 C77.2 J3.3 L1.1 L2.1 L3.1 L4.1 R1.1 R2.1 R3.1 R4.1 R5.1 R6.2 R7.1 R11.1 R32.1 R33.1 R42.2 U2.2(VIN) U3.3(D) U4.5(PWR) U9.1(VCCA) U9.2(1DIR) U9.3(2DIR) U10.1(VCCA) U11.1(VCC) U14.5(PWR)
P12V: C9.2 C17.2 C18.2 C86.1 C87.1 C88.2 C93.2 J500.C35(12P0V) J500.C37(12P0V) R50.2 R53.1 U1.6(IN) U5.4(/MR) U5.5(VCC) U7.11(12V) U7.48(12V) U7.50(12V) U13.13(VIN) U13.14(VIN) U15.2(S) U17.1(VIN)
VCC2: C11.2 C31.2 C32.2 C33.2 C34.2 C35.2 C36.2 C37.2 C38.2 C39.2 C40.2 C41.2 C42.2 C94.2 R8.2 R10.1 R55.2 TP4.1 U1.1(OUT) U8.A3(VCC2) U8.A4(VCC2) U8.A25(VCC2) U8.AA3(VCC2) U8.AA4(VCC2) U8.AA25(VCC2) U8.B26(VCC2) U8.L26(VCC2) U8.M26(VCC2) U8.N26(VCC2) U8.Z26(VCC2) U17.2(VOUT)
VCC2_EN: R11.2 TP6.1 U1.4(EN) U2.5(ERROR) U4.4(Y) U17.5(EN)
3P3VAUX: J500.D32(3P3VAUX)
DAD_ADDR_0: J500.A14(DP4_M2C_P) U7.19(A0)
DAD_ADDR_1: J500.A18(DP5_M2C_P) U7.18(A1)
DAD_ADDR_2: J500.A22(DP1_C2M_P) U7.17(A2)
DAD_ADDR_3: J500.A26(DP2_C2M_P) U7.16(A3)
DAD_IRQZ: J500.B08(DP8_M2C_P) R1.2 U7.43(IRQZ)
DAD_MODE_0: J500.A06(DP2_M2C_P) U7.3(MODE0)
DAD_MODE_1: J500.A10(DP3_M2C_P) U7.2(MODE1)
DAD_OEZ: J500.B04(DP9_M2C_P) R2.2 U7.6(OEZ)
DAD_SEL_0: J500.A30(DP3_C2M_P) U7.5(SEL0)
DAD_SEL_1: J500.A34(DP4_C2M_P) U7.4(SEL1)
DAD_STRB: J500.A38(DP5_C2M_P) U7.15(STROBE)
DMD_RSTZ: J500.A02(DP1_M2C_P) R26.2 U7.59(RESETZ) U9.4(1A1)
DMD_RSTZ_1V8: R22.1 U8.G4(PWRDNZ)
DMD_TEMP_N: C78.1 R35.1 U8.W16(TEMP_N)
DMD_TEMP_P: C78.2 R34.1 U8.W17(TEMP_P)
I2C_SCL_3P3V: J3.1 R32.2 U11.8(SCL)
I2C_SDA_3P3V: J3.2 R33.2 U11.7(SDA)
M_DCLKA_N: J500.K05(CLK2_M2C_N) U8.H23(DCLK_CN)
M_DCLKA_P: J500.K04(CLK2_M2C_P) U8.G23(DCLK_CP)
M_DCLKB_N: J500.J03(CLK3_M2C_N) U8.T23(DCLK_DN)
M_DCLKB_P: J500.J02(CLK3_M2C_P) U8.U23(DCLK_DP)
M_DDA00_N: J500.D21(LA17_N_CC) U8.B18(D_CN<0>)
M_DDA00_P: J500.D20(LA17_P_CC) U8.B19(D_CP<0>)
M_DDA01_N: J500.C23(LA18_N_CC) U8.H24(D_CN<1>)
M_DDA01_P: J500.C22(LA18_P_CC) U8.G24(D_CP<1>)
M_DDA02_N: J500.H23(LA19_N) U8.L23(D_CN<2>)
M_DDA02_P: J500.H22(LA19_P) U8.K23(D_CP<2>)
M_DDA03_N: J500.G22(LA20_N) U8.C18(D_CN<3>)
M_DDA03_P: J500.G21(LA20_P) U8.C19(D_CP<3>)
M_DDA04_N: J500.H26(LA21_N) U8.A19(D_CN<4>)
M_DDA04_P: J500.H25(LA21_P) U8.A20(D_CP<4>)
M_DDA05_N: J500.G25(LA22_N) U8.E24(D_CN<5>)
M_DDA05_P: J500.G24(LA22_P) U8.D24(D_CP<5>)
M_DDA06_N: J500.D24(LA23_N) U8.K25(D_CN<6>)
M_DDA06_P: J500.D23(LA23_P) U8.J25(D_CP<6>)
M_DDA07_N: J500.H29(LA24_N) U8.C26(D_CN<7>)
M_DDA07_P: J500.H28(LA24_P) U8.D26(D_CP<7>)
M_DDA08_N: J500.G28(LA25_N) U8.C21(D_CN<8>)
M_DDA08_P: J500.G27(LA25_P) U8.B21(D_CP<8>)
M_DDA09_N: J500.D27(LA26_N) U8.G25(D_CN<9>)
M_DDA09_P: J500.D26(LA26_P) U8.F25(D_CP<9>)
M_DDA10_N: J500.C27(LA27_N) U8.A24(D_CN<10>)
M_DDA10_P: J500.C26(LA27_P) U8.B24(D_CP<10>)
M_DDA11_N: J500.H32(LA28_N) U8.J26(D_CN<11>)
M_DDA11_P: J500.H31(LA28_P) U8.K26(D_CP<11>)
M_DDA12_N: J500.G31(LA29_N) U8.D25(D_CN<12>)
M_DDA12_P: J500.G30(LA29_P) U8.C25(D_CP<12>)
M_DDA13_N: J500.H35(LA30_N) U8.E23(D_CN<13>)
M_DDA13_P: J500.H34(LA30_P) U8.D23(D_CP<13>)
M_DDA14_N: J500.G34(LA31_N) U8.B23(D_CN<14>)
M_DDA14_P: J500.G33(LA31_P) U8.C23(D_CP<14>)
M_DDA15_N: J500.H38(LA32_N) U8.K24(D_CN<15>)
M_DDA15_P: J500.H37(LA32_P) U8.L24(D_CP<15>)
M_DDB00_N: J500.K26(HB00_CC_N) U8.Z18(D_DN<0>)
M_DDB00_P: J500.K25(HB00_CC_P) U8.Z19(D_DP<0>)
M_DDB01_N: J500.J25(HB01_N) U8.T24(D_DN<1>)
M_DDB01_P: J500.J24(HB01_P) U8.U24(D_DP<1>)
M_DDB02_N: J500.F23(HB02_N) U8.N23(D_DN<2>)
M_DDB02_P: J500.F22(HB02_P) U8.P23(D_DP<2>)
M_DDB03_N: J500.E22(HB03_N) U8.Y18(D_DN<3>)
M_DDB03_P: J500.E21(HB03_P) U8.Y19(D_DP<3>)
M_DDB04_N: J500.F26(HB04_N) U8.AA19(D_DN<4>)
M_DDB04_P: J500.F25(HB04_P) U8.AA20(D_DP<4>)
M_DDB05_N: J500.E25(HB05_N) U8.W24(D_DN<5>)
M_DDB05_P: J500.E24(HB05_P) U8.X24(D_DP<5>)
M_DDB06_N: J500.K29(HB06_N_CC) U8.P25(D_DN<6>)
M_DDB06_P: J500.K28(HB06_P_CC) U8.R25(D_DP<6>)
M_DDB07_N: J500.J28(HB07_N) U8.Y26(D_DN<7>)
M_DDB07_P: J500.J27(HB07_P) U8.X26(D_DP<7>)
M_DDB08_N: J500.F29(HB08_N) U8.Y21(D_DN<8>)
M_DDB08_P: J500.F28(HB08_P) U8.Z21(D_DP<8>)
M_DDB09_N: J500.E28(HB09_N) U8.U25(D_DN<9>)
M_DDB09_P: J500.E27(HB09_P) U8.V25(D_DP<9>)
M_DDB10_N: J500.K32(HB10_N) U8.AA24(D_DN<10>)
M_DDB10_P: J500.K31(HB10_P) U8.Z24(D_DP<10>)
M_DDB11_N: J500.J31(HB11_N) U8.R26(D_DN<11>)
M_DDB11_P: J500.J30(HB11_P) U8.P26(D_DP<11>)
M_DDB12_N: J500.F32(HB12_N) U8.X25(D_DN<12>)
M_DDB12_P: J500.F31(HB12_P) U8.Y25(D_DP<12>)
M_DDB13_N: J500.E31(HB13_N) U8.W23(D_DN<13>)
M_DDB13_P: J500.E30(HB13_P) U8.X23(D_DP<13>)
M_DDB14_N: J500.K35(HB14_N) U8.Z23(D_DN<14>)
M_DDB14_P: J500.K34(HB14_P) U8.Y23(D_DP<14>)
M_DDB15_N: J500.J34(HB15_N) U8.P24(D_DN<15>)
M_DDB15_P: J500.J33(HB15_P) U8.N24(D_DP<15>)
M_SCTRLA_N: J500.G37(LA33_N) U8.F26(SCTRL_CN)
M_SCTRLA_P: J500.G36(LA33_P) U8.G26(SCTRL_CP)
M_SCTRLB_N: J500.F35(HB16_N) U8.V26(SCTRL_DN)
M_SCTRLB_P: J500.F34(HB16_P) U8.U26(SCTRL_DP)
MBRST0: TP23.1 U7.22(OUT0) U8.E14(MBRST<0>)
MBRST1: TP22.1 U7.24(OUT1) U8.D13(MBRST<1>)
MBRST2: TP21.1 U7.27(OUT2) U8.E13(MBRST<2>)
MBRST3: TP20.1 U7.29(OUT3) U8.C12(MBRST<3>)
MBRST4: TP19.1 U7.32(OUT4) U8.E12(MBRST<4>)
MBRST5: TP18.1 U7.34(OUT5) U8.C11(MBRST<5>)
MBRST6: TP17.1 U7.37(OUT6) U8.D16(MBRST<6>)
MBRST7: TP16.1 U7.39(OUT7) U8.C15(MBRST<7>)
MBRST8: TP15.1 U7.62(OUT8) U8.W14(MBRST<8>)
MBRST9: TP14.1 U7.64(OUT9) U8.X13(MBRST<9>)
MBRST10: TP13.1 U7.67(OUT10) U8.W13(MBRST<10>)
MBRST11: TP11.1 U7.69(OUT11) U8.Y12(MBRST<11>)
MBRST12: TP10.1 U7.72(OUT12) U8.W12(MBRST<12>)
MBRST13: TP9.1 U7.74(OUT13) U8.Y11(MBRST<13>)
MBRST14: TP8.1 U7.77(OUT14) U8.Y15(MBRST<14>)
MBRST15: TP7.1 U7.79(OUT15) U8.X16(MBRST<15>)
MODEB: J500.B12(DP7_M2C_P) TP1.1
P3P3V1: C2.2 J500.C39(3P3V) L1.2
P3P3V2: C6.2 J500.D36(3P3V) L3.2
P3P3V3: C3.2 J500.D38(3P3V) L2.2
P3P3V4: C7.2 J500.D40(3P3V) L4.2
RES0: J500.B40(RES0)
RES1: J500.B01(RES1)
S_DCLKA_N: J500.H05(CLK0_M2C_N) U8.B3(DCLK_AN)
S_DCLKA_P: J500.H04(CLK0_M2C_P) U8.C3(DCLK_AP)
S_DCLKB_N: J500.G03(CLK1_M2C_N) U8.Y4(DCLK_BN)
S_DCLKB_P: J500.G02(CLK1_M2C_P) U8.Y5(DCLK_BP)
S_DDA00_N: J500.G07(LA00_N_CC) U8.E10(D_AN<0>)
S_DDA00_P: J500.G06(LA00_P_CC) U8.E11(D_AP<0>)
S_DDA01_N: J500.D09(LA01_N_CC) U8.D6(D_AN<1>)
S_DDA01_P: J500.D08(LA01_P_CC) U8.C6(D_AP<1>)
S_DDA02_N: J500.H08(LA02_N) U8.E3(D_AN<2>)
S_DDA02_P: J500.H07(LA02_P) U8.D3(D_AP<2>)
S_DDA03_N: J500.G10(LA03_N) U8.C7(D_AN<3>)
S_DDA03_P: J500.G09(LA03_P) U8.C8(D_AP<3>)
S_DDA04_N: J500.H11(LA04_N) U8.D8(D_AN<4>)
S_DDA04_P: J500.H10(LA04_P) U8.D7(D_AP<4>)
S_DDA05_N: J500.D12(LA05_N) U8.E6(D_AN<5>)
S_DDA05_P: J500.D11(LA05_P) U8.E5(D_AP<5>)
S_DDA06_N: J500.C11(LA06_N) U8.C5(D_AN<6>)
S_DDA06_P: J500.C10(LA06_P) U8.C4(D_AP<6>)
S_DDA07_N: J500.H14(LA07_N) U8.B8(D_AN<7>)
S_DDA07_P: J500.H13(LA07_P) U8.B9(D_AP<7>)
S_DDA08_N: J500.G13(LA08_N) U8.B6(D_AN<8>)
S_DDA08_P: J500.G12(LA08_P) U8.B5(D_AP<8>)
S_DDA09_N: J500.D15(LA09_N) U8.C10(D_AN<9>)
S_DDA09_P: J500.D14(LA09_P) U8.B10(D_AP<9>)
S_DDA10_N: J500.C15(LA10_N) U8.A9(D_AN<10>)
S_DDA10_P: J500.C14(LA10_P) U8.A10(D_AP<10>)
S_DDA11_N: J500.H17(LA11_N) U8.C13(D_AN<11>)
S_DDA11_P: J500.H16(LA11_P) U8.C14(D_AP<11>)
S_DDA12_N: J500.G16(LA12_N) U8.B12(D_AN<12>)
S_DDA12_P: J500.G15(LA12_P) U8.B13(D_AP<12>)
S_DDA13_N: J500.D18(LA13_N) U8.C17(D_AN<13>)
S_DDA13_P: J500.D17(LA13_P) U8.C16(D_AP<13>)
S_DDA14_N: J500.C19(LA14_N) U8.B15(D_AN<14>)
S_DDA14_P: J500.C18(LA14_P) U8.B16(D_AP<14>)
S_DDA15_N: J500.H20(LA15_N) U8.D15(D_AN<15>)
S_DDA15_P: J500.H19(LA15_P) U8.E15(D_AP<15>)
S_DDB00_N: J500.F05(HA00_N_CC) U8.W10(D_BN<0>)
S_DDB00_P: J500.F04(HA00_P_CC) U8.W11(D_BP<0>)
S_DDB01_N: J500.E03(HA01_N_CC) U8.Z3(D_BN<1>)
S_DDB01_P: J500.E02(HA01_P_CC) U8.Y3(D_BP<1>)
S_DDB02_N: J500.K08(HA02_N) U8.W4(D_BN<2>)
S_DDB02_P: J500.K07(HA02_P) U8.X4(D_BP<2>)
S_DDB03_N: J500.J07(HA03_N) U8.Y7(D_BN<3>)
S_DDB03_P: J500.J06(HA03_P) U8.Y8(D_BP<3>)
S_DDB04_N: J500.F08(HA04_N) U8.X8(D_BN<4>)
S_DDB04_P: J500.F07(HA04_P) U8.X7(D_BP<4>)
S_DDB05_N: J500.E07(HA05_N) U8.Y6(D_BN<5>)
S_DDB05_P: J500.E06(HA05_P) U8.X6(D_BP<5>)
S_DDB06_N: J500.K11(HA06_N) U8.X3(D_BN<6>)
S_DDB06_P: J500.K10(HA06_P) U8.W3(D_BP<6>)
S_DDB07_N: J500.J10(HA07_N) U8.Z8(D_BN<7>)
S_DDB07_P: J500.J09(HA07_P) U8.Z9(D_BP<7>)
S_DDB08_N: J500.F11(HA08_N) U8.Z6(D_BN<8>)
S_DDB08_P: J500.F10(HA08_P) U8.Z5(D_BP<8>)
S_DDB09_N: J500.E10(HA09_N) U8.Y10(D_BN<9>)
S_DDB09_P: J500.E09(HA09_P) U8.Z10(D_BP<9>)
S_DDB10_N: J500.K14(HA10_N) U8.AA9(D_BN<10>)
S_DDB10_P: J500.K13(HA10_P) U8.AA10(D_BP<10>)
S_DDB11_N: J500.J13(HA11_N) U8.Y13(D_BN<11>)
S_DDB11_P: J500.J12(HA11_P) U8.Y14(D_BP<11>)
S_DDB12_N: J500.F14(HA12_N) U8.Z12(D_BN<12>)
S_DDB12_P: J500.F13(HA12_P) U8.Z13(D_BP<12>)
S_DDB13_N: J500.E13(HA13_N) U8.Y17(D_BN<13>)
S_DDB13_P: J500.E12(HA13_P) U8.Y16(D_BP<13>)
S_DDB14_N: J500.J16(HA14_N) U8.Z15(D_BN<14>)
S_DDB14_P: J500.J15(HA14_P) U8.Z16(D_BP<14>)
S_DDB15_N: J500.F17(HA15_N) U8.X15(D_BN<15>)
S_DDB15_P: J500.F16(HA15_P) U8.W15(D_BP<15>)
S_SCTRLA_N: J500.G19(LA16_N) U8.E4(SCTRL_AN)
S_SCTRLA_P: J500.G18(LA16_P) U8.D4(SCTRL_AP)
S_SCTRLB_N: J500.E16(HA16_N) U8.W5(SCTRL_BN)
S_SCTRLB_P: J500.E15(HA16_P) U8.W6(SCTRL_BP)
SCP_CLK: J500.B32(DP7_C2M_P) R27.2 U7.56(SCPCK) U9.5(1A2)
SCP_CLK_1V8: R23.1 U8.U2(SCPCLK)
SCP_DAD_CSZ: J500.B24(DP9_C2M_P) R3.2 U7.58(SCPENZ)
SCP_DMD_CSZ: J500.C06(DP0_M2C_P) R4.2 R29.2 U9.7(2A2) U10.5(DIR)
SCP_DMD_CSZ_1V8: R25.1 U8.U4(SCPENZ)
SCP_MISO: J500.B36(DP6_C2M_P) R5.2 R16.2 R30.2
SCP_MISO_1V8: R31.2 U8.U3(SCPDO) U10.4(B)
SCP_MOSI: J500.C02(DP0_C2M_P) R28.2 U7.57(SCPDI) U9.6(2A1)
SCP_MOSI_1V8: R24.1 U8.T3(SCPDI)
V_OFFSET: C13.2 C14.2 C15.2 C16.2 D1.2(CATHODE) R12.2 R51.2 R54.1 TP24.1 U7.23(VOFFSET_RAIL) U7.28(VOFFSET_RAIL) U7.33(VOFFSET_RAIL) U7.38(VOFFSET_RAIL) U7.49(VOFFSET) U7.63(VOFFSET_RAIL) U7.68(VOFFSET_RAIL) U7.73(VOFFSET_RAIL) U7.78(VOFFSET_RAIL)
VADJ: J500.E39(VADJ) J500.F40(VADJ) J500.G39(VADJ) J500.H40(VADJ)
VBIAS: C25.2 C26.2 C27.2 C28.2 D3.C R49.2 TP26.1 U7.9(VBIAS) U7.21(VBAIS_RAIL) U7.30(VBIAS_RAIL) U7.31(VBIAS_RAIL) U7.40(VBIAS_RAIL) U7.61(VBIAS_RAIL) U7.70(VBIAS_RAIL) U7.71(VBIAS_RAIL) U7.80(VBIAS_RAIL)
VIO_B_M2C: J500.J39(VIO_B_M2C) J500.K40(VIO_B_M2C)
VR_PG: D5.C R43.2 TP40.1
VR_PG_NEG: R42.1 R43.1 U13.8(PGOOD)
VREF_A_M2C: J500.H01(VREF_A_M2C)
VREF_B_M2C: J500.K01(VREF_B_M2C)
VRESET_DAD: C21.2 C22.2 C23.2 C24.2 D2.A R41.1 TP27.1 U7.13(VRESET)
VRESET_EN: D7.2(CATHODE) R48.1 R52.1 R53.2 R54.2 U13.12(EN) U15.3(D)
VRESET_EXT: C80.1 C81.1 C82.1 C83.1 C84.1 C85.1 C88.1 C90.1 C91.1 C92.1 D6.A D7.1(ANODE) R20.1 R45.1 R46.1 R47.1 R48.2 TP41.1 U13.10(AGND) U13.15(PGND) U13.16(PGND) U13.17(PAD)
VRESET_RAIL: R20.2 R41.2 TP25.1 U7.25(VRESET_RAIL) U7.26(VRESET_RAIL) U7.35(VRESET_RAIL) U7.36(VRESET_RAIL) U7.65(VRESET_RAIL) U7.66(VRESET_RAIL) U7.75(VRESET_RAIL) U7.76(VRESET_RAIL) U7.81(PAD)
N16506021: R21.2 TP30.1 U8.W18(PROG_FUSE_EN)
N16506047: TP33.1 U8.G3(SCP_TEST_MUX)
N16506207: TP32.1 U8.D17(BIST_D)
N16506209: TP31.1 U8.X17(BIST_C)
N16506211: TP29.1 U8.K4(BIST_B)
N16506213: TP28.1 U8.P4(BIST_A)
N16506277: TP34.1 U8.H3(TP0)
N16506279: TP35.1 U8.G2(TP1)
N16506281: TP36.1 U8.F3(TP2)
N16551414: D3.A L6.1 U7.8(VBIAS_SWL)
N16555452: C29.2 C30.2 L6.2 U7.10(VBIAS_LHI)
N16558116: D2.C L5.2 U7.12(VRESET_SWL)
N16559232: C19.2 C20.2 U7.47(V5REG)
N16562882: R17.2 U7.45(DEV_ID1)
N16562886: R18.2 U7.44(DEV_ID0)
N16780954: R6.1 TP3.1 U2.1(EN)
N16783652: R16.1 U7.42(SCPDO)
N16819402: R19.1 U7.54(NC)
N16824071: R8.1 R9.2 U1.2(FB)
N16824656: R7.2 TP2.1 U1.3(PG)
N16836860: R12.1 R13.1 U3.1(G)
N16836862: R14.1 U3.2(S) U4.2(A)
N16841509: R10.2 U6.3(D)
N16842070: R15.1 U5.1(/RESET) U14.2(A)
N16883881: R34.2 U11.2(D+)
N16883883: TP37.1 U11.6(ALERT)
N16883884: R35.2 U11.3(D-)
N16883892: TP38.1 U11.4(THERM)
N16884055: R22.2 U9.13(1B1)
N16884056: R23.2 U9.12(1B2)
N16884057: R24.2 U9.11(2B1)
N16884058: R25.2 U9.10(2B2)
N16884072: R30.1 U10.3(A)
N16949503: C79.2 U13.3(CBOOT)
N16949505: C79.1 L7.1 U13.1(SW) U13.2(SW)
N16949620: C89.1 R44.2 R47.2 U13.9(FB)
N16949632: R45.2 U13.7(RT)
N16949636: C90.2 U13.4(VCC)
N16949644: R46.2 U13.6(SYNC)
N16949726: C91.2 U13.11(SS/TRK)
N16949871: R49.1 R51.1 U16.1(G)
N16949907: R50.1 U15.1(G) U16.3(D)
N16950963: U6.1(G) U14.4(Y)
N16971448: R55.1 R56.2 U17.4(FB)

Not connected (* = marked no-connect by the designer): J500 B16(DP6_M2C_P)* B17(DP6_M2C_N)* B20(GBTCLK1_M2C_P)* B21(GBTCLK1_M2C_N)* B25(DP9_C2M_N)* B28(DP8_C2M_P)* B29(DP8_C2M_N)* C30(SCL)* C31(SDA)* C34(GA0)* D01(PG_C2M)* D04(GBTCLK0_M2C_P)* D05(GBTCLK0_M2C_N)* D29(TCK)* D30(TDI)* D31(TDO)* D33(TMS)* D34(TRST_L)* D35(GA1)* E18(HA20_P)* E19(HA20_N)* E33(HB19_P)* E34(HB19_N)* E36(HB21_P)* E37(HB21_N)* F01(PG_M2C)* F19(HA19_P)* F20(HA19_N)* F37(HB20_P)* F38(HB20_N)* H02(PRSNT_M2C_L)* J18(HA18_P)* J19(HA18_N)* J21(HA22_P)* J22(HA22_N)* J36(HB18_P)* J37(HB18_N)* K16(HA17_P_CC)* K17(HA17_N_CC)* K19(HA21_P)* K20(HA21_N)* K22(HA23_P)* K23(HA23_N)* K37(HB17_P_CC)* K38(HB17_N_CC)*; U5 3(NC)*; U7 51(NC)* 52(NC)*; U8 G1(G1_NC)* H1(H1_NC)* J1(J1_NC)* J3(J3_NC)* J4(J4_NC)* K3(K3_NC)* P3(P3_NC)* R1(R1_NC)* R3(R3_NC)* R4(R4_NC)* T1(T1_NC)* U1(U1_NC)* V3(V3_NC)*

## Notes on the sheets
sheet 1
- Main Controller Bus B
- Secondary Controller Bus B
- Secondary Controller Bus A
- Main Controller Bus A
- Total Power Transfer:
  1A at 12V
- (C) COPYRIGHT 2023
         Texas Instruments
        All Rights Reserved
sheet 2
- CONTENTS:
  PG01: TITLE
  PG02: POWER
  PG03: DMD
  PG04: LEVEL SHIFT, TEMP SNS, I2C
  PG05: INPUT FMC CONNECTOR
  PG06: REVISION HISTORY
  PG07: IMPORTANT NOTICE
- Cadence Capture V.17.2
- 7
sheet 3
- REVISIONS:
  REV A: INITIAL ENGINEERING RELEASE
- (C) COPYRIGHT 2023
         Texas Instruments
        All Rights Reserved
sheet 4
- 10 V @ 300 mA
- 1.8V @ 3A
- 12V UVLO MONITOR
- U17 added due to inavailability of TPS7A25.
  Install only one supply for VCC2
- 10 V @ 1000 mA
- 11V Protection Zener Diode
  V_offset = 10V
- 1-G
- 3-D
- 2-S
- 1-G
- 3-D
- 2-S
- POWER
- (C) COPYRIGHT 2023
         Texas Instruments
        All Rights Reserved
sheet 5
- DMD
- (C) COPYRIGHT 2023
         Texas Instruments
        All Rights Reserved
sheet 6
- 3.3V I2C Connector
- I2C ADDRESS 1001 100_
- DMD
- (C) COPYRIGHT 2023
         Texas Instruments
        All Rights Reserved
sheet 7
- (C) COPYRIGHT 2023
         Texas Instruments
        All Rights Reserved
